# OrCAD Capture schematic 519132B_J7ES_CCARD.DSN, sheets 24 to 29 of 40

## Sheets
24 24. PMIC B: size C; rev: A
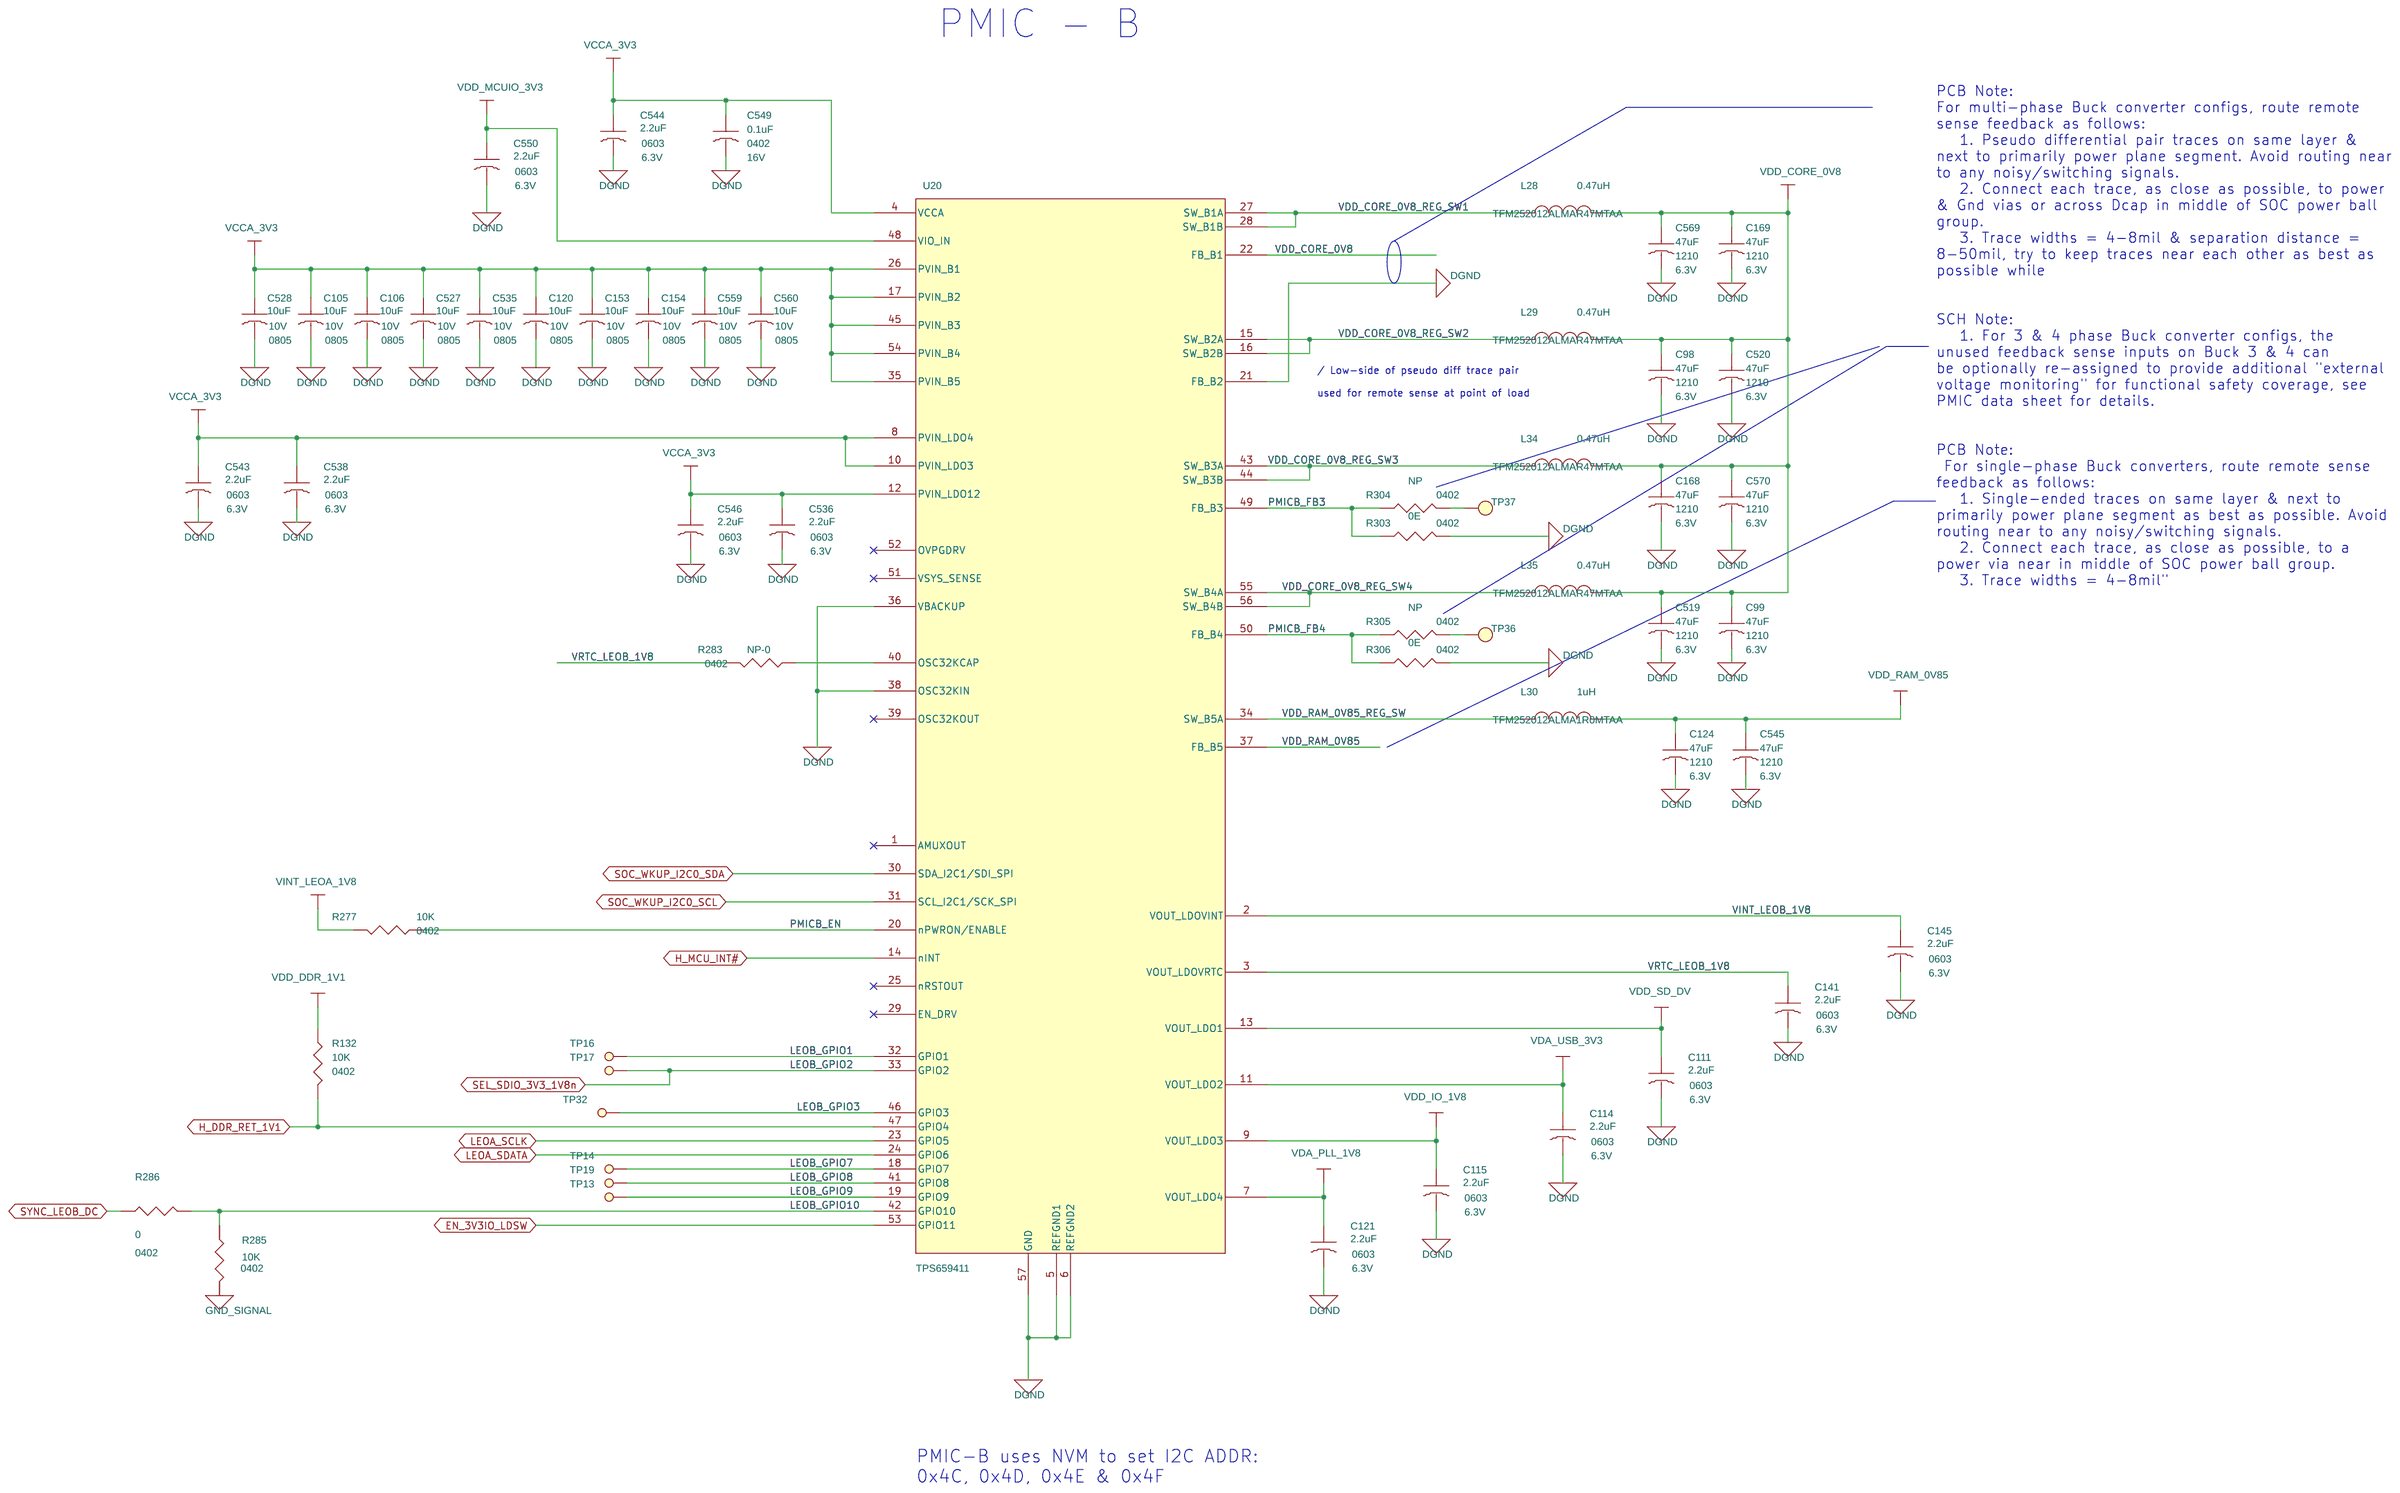
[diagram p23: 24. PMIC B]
25 25. LOAD SWITCHES: size C; rev: A
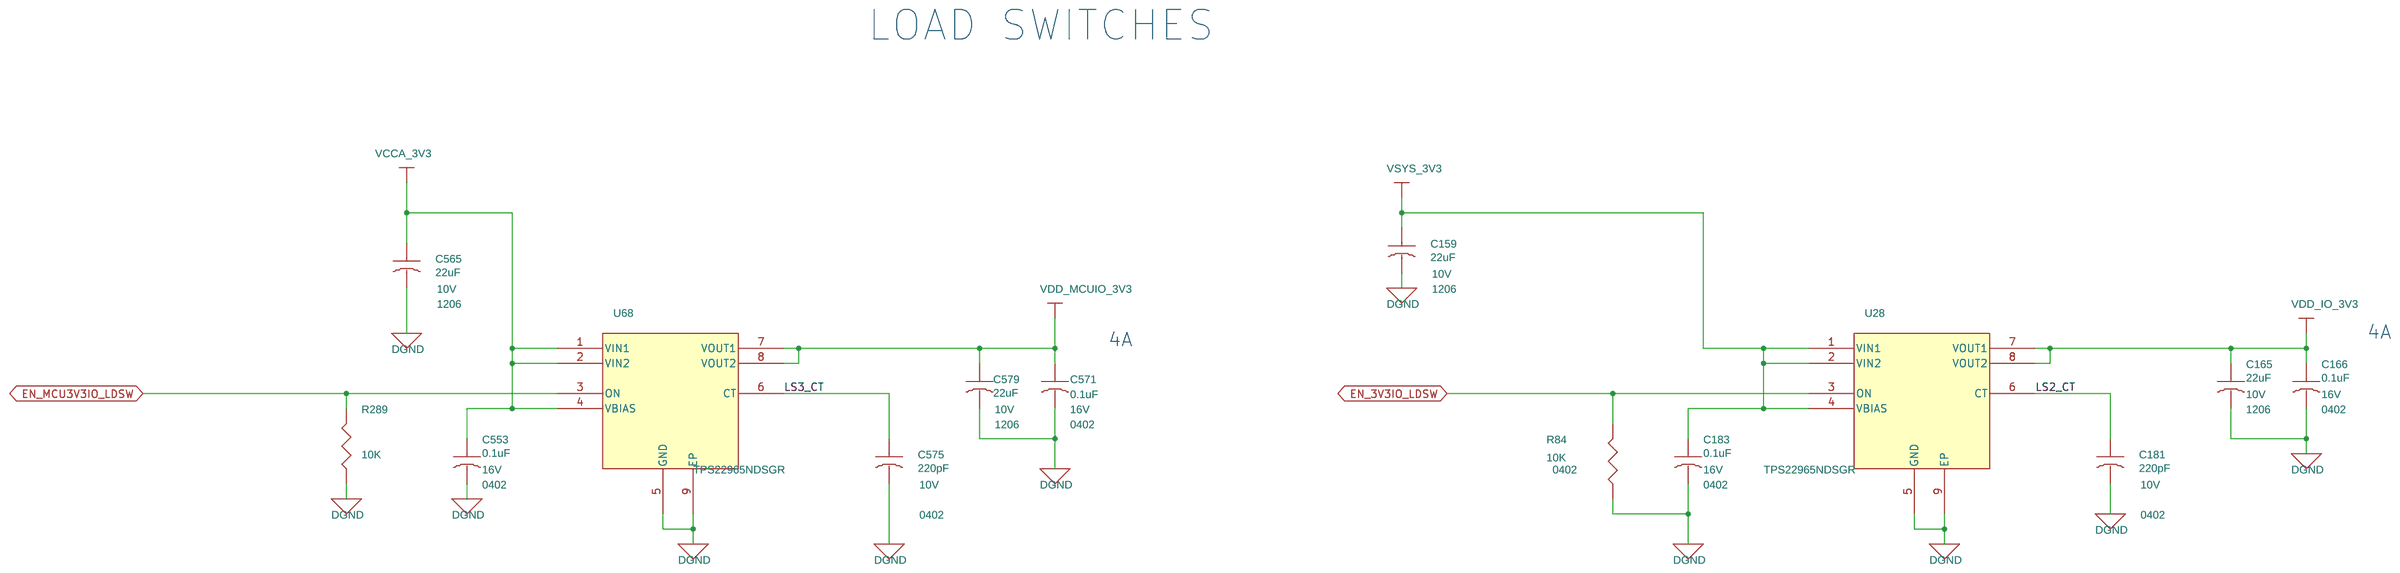
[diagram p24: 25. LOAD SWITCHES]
26 27. BOOTMODE SWITCH: size C; rev: A
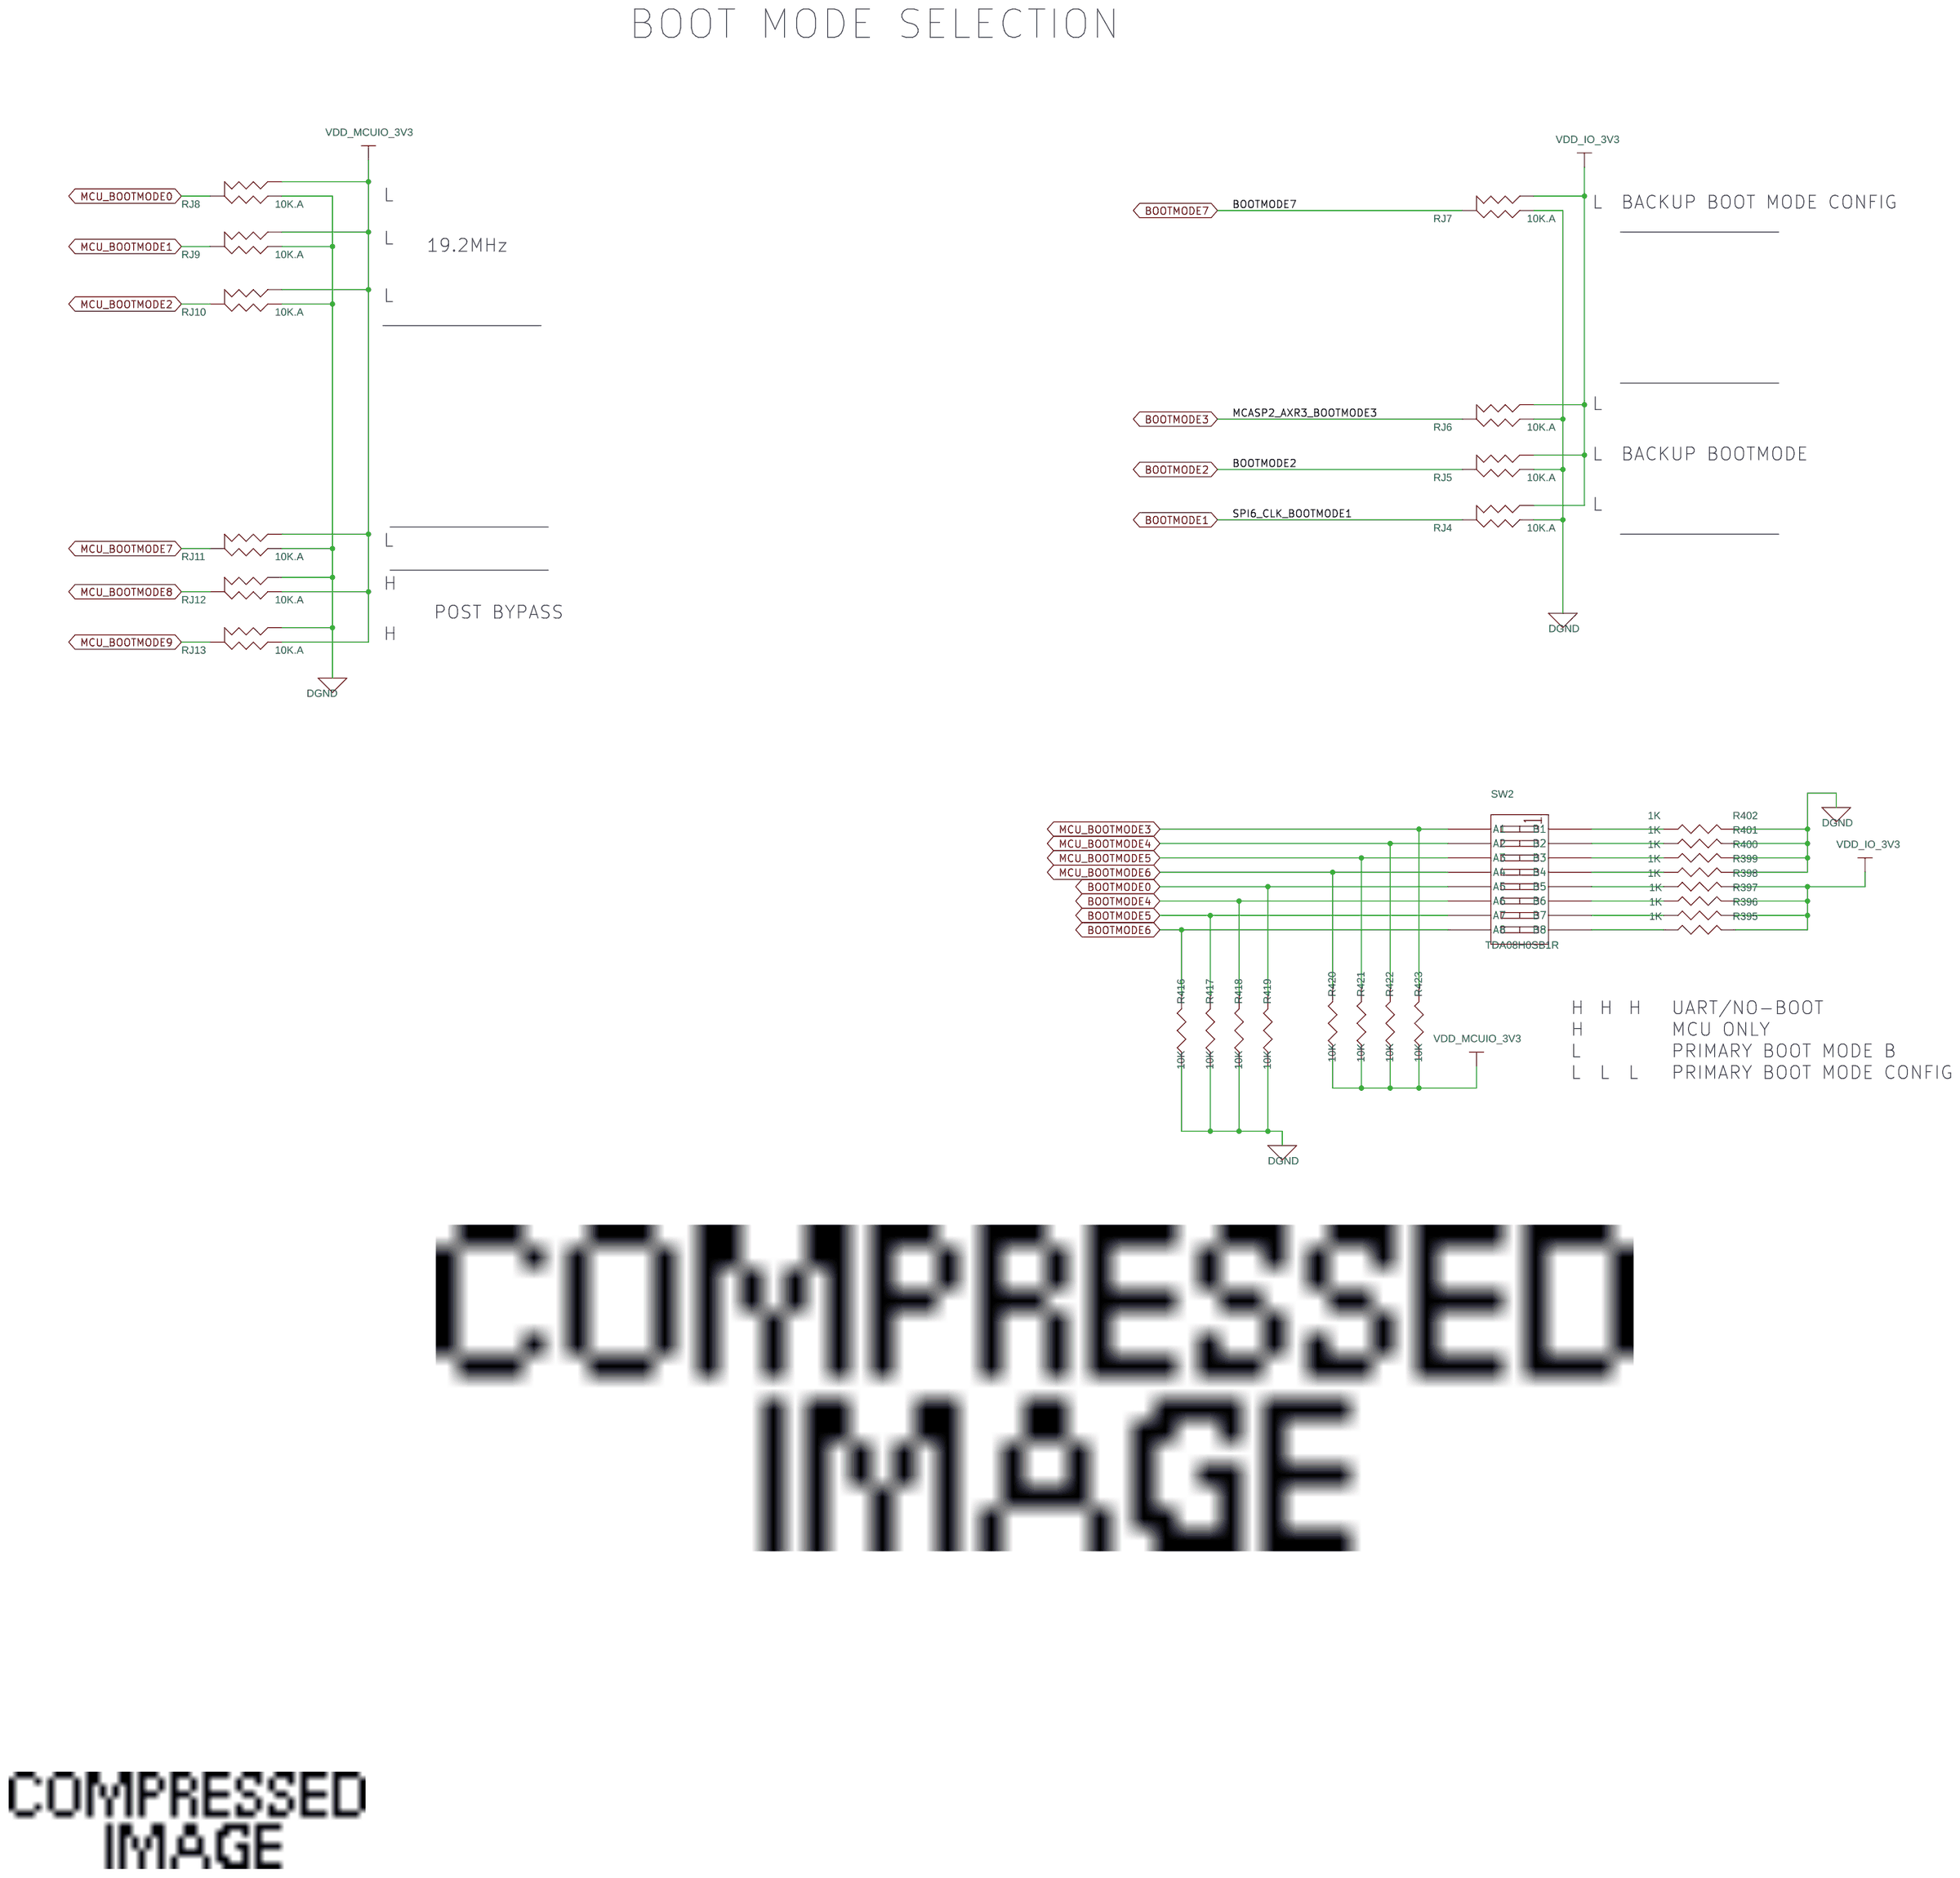
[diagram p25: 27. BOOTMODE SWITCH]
27 28.MEM eMMC: size C; rev: A
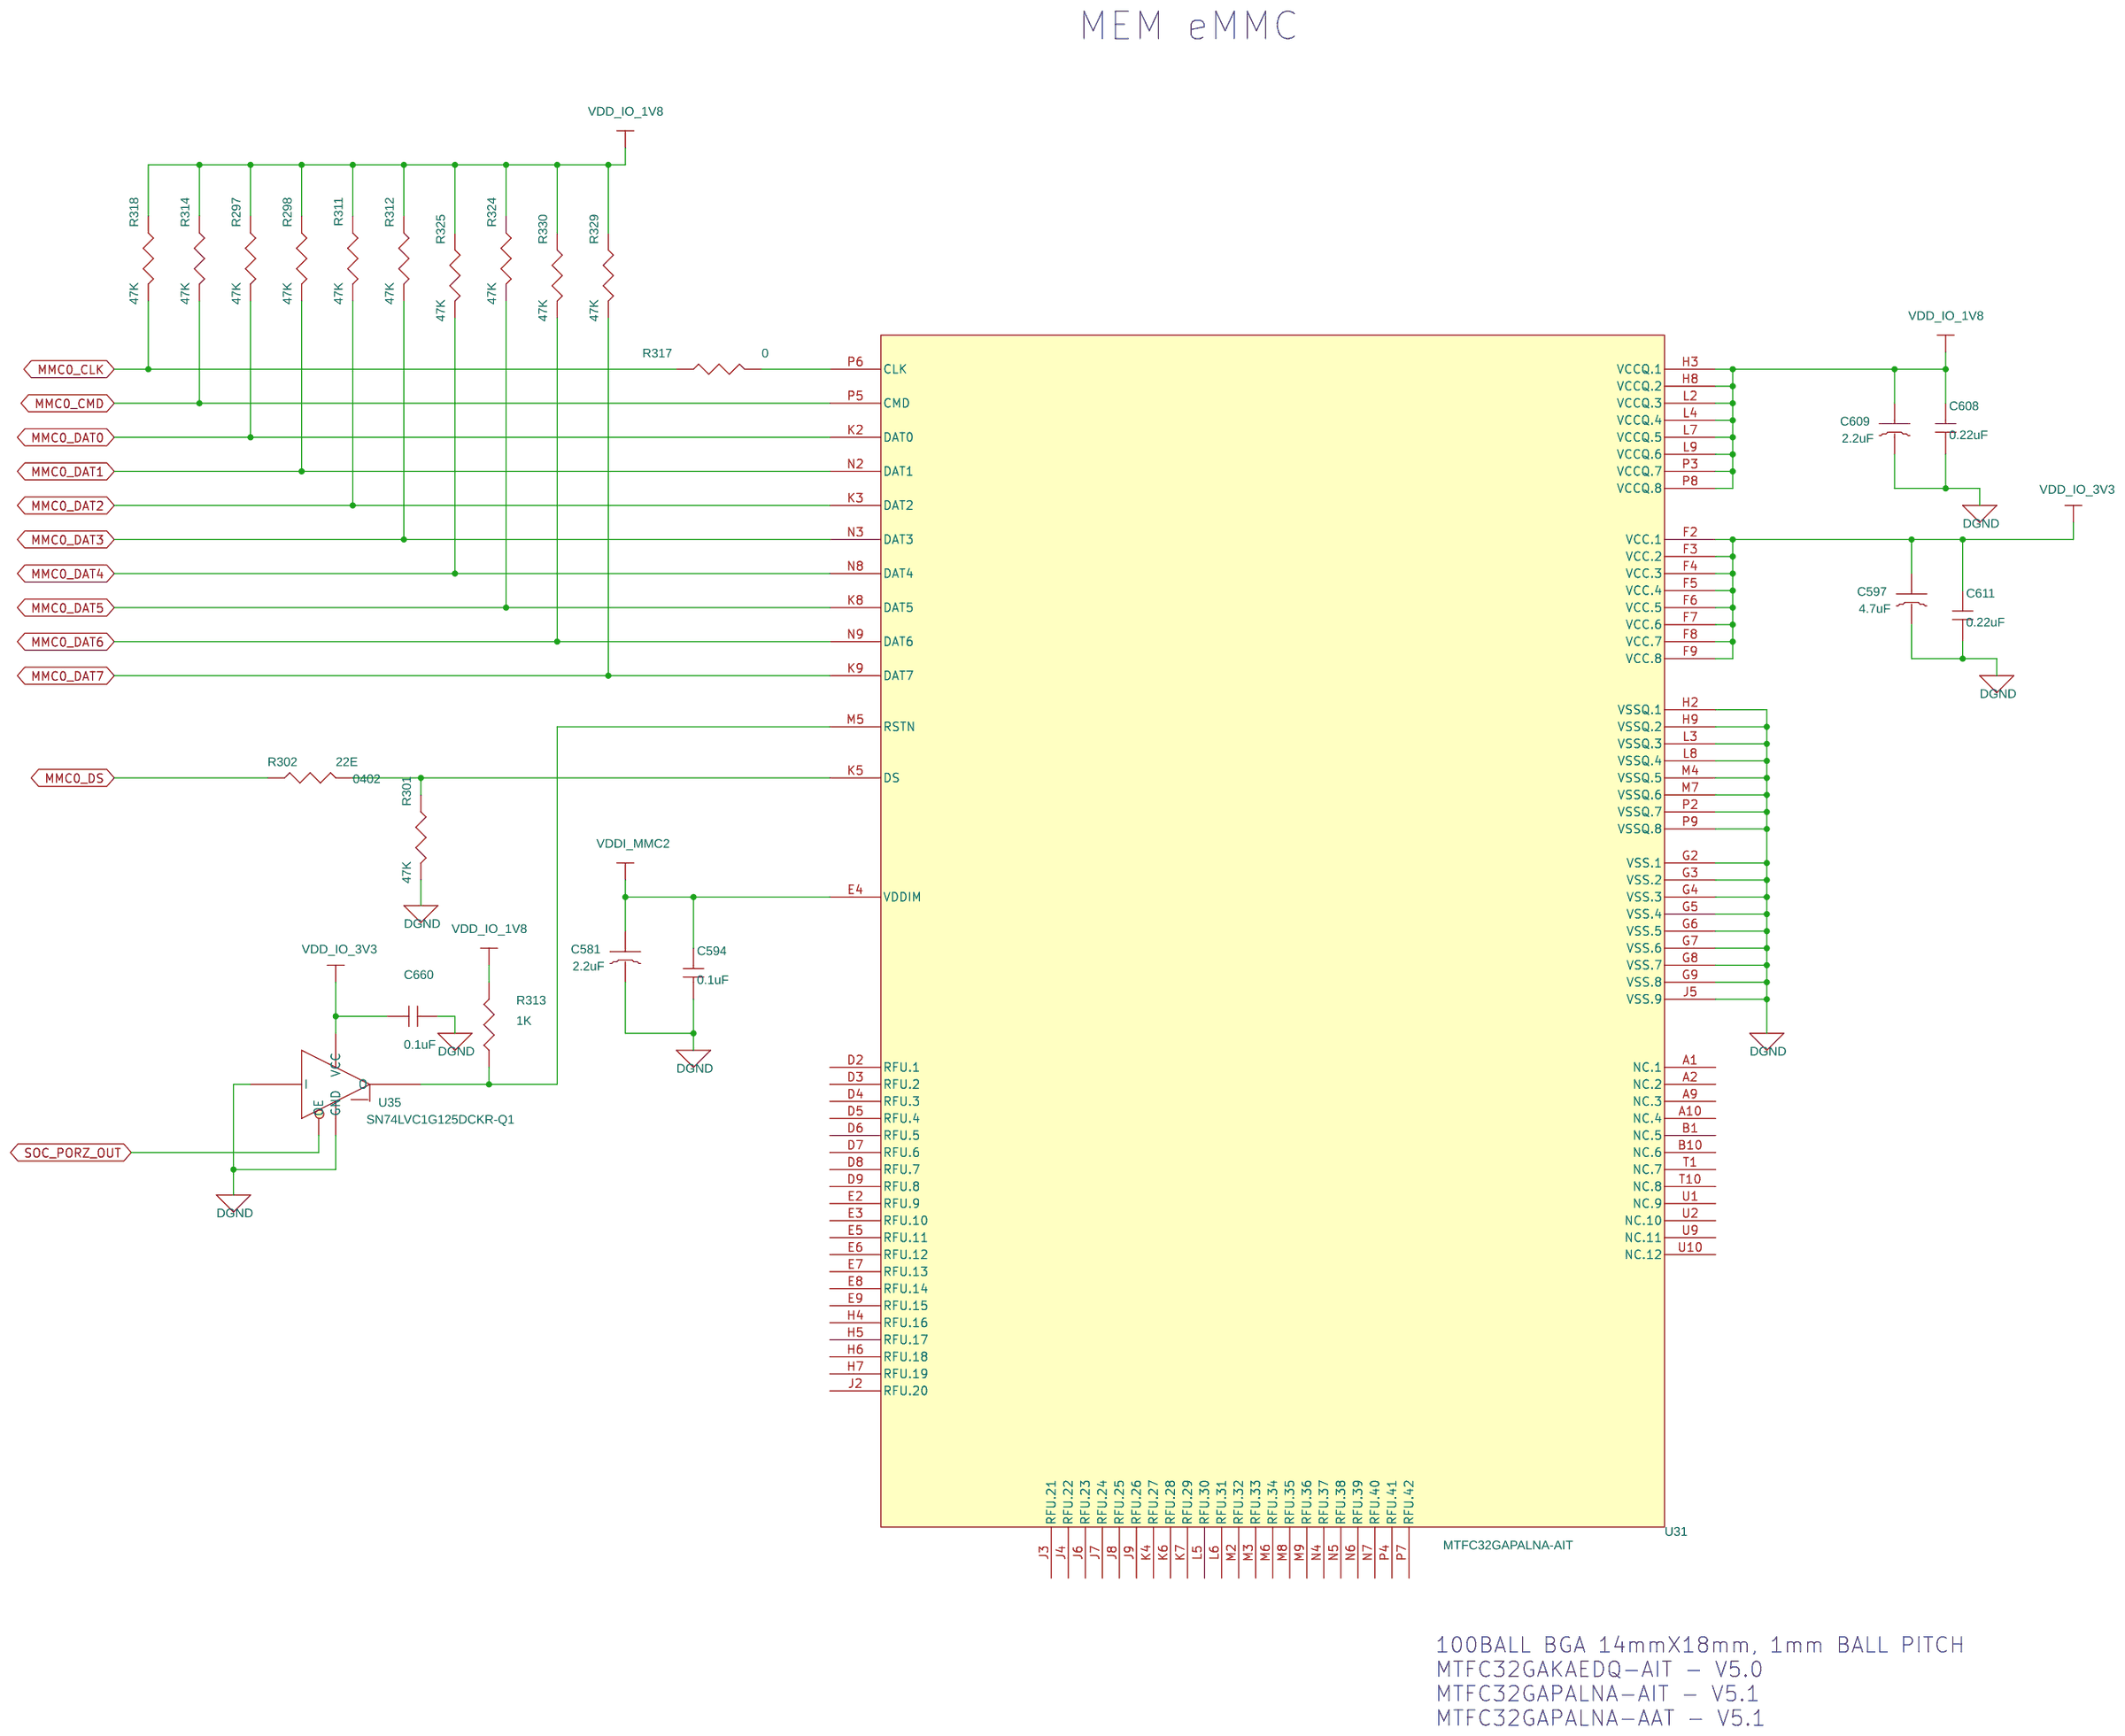
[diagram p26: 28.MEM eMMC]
28 29.USB MEDIA: size C; rev: A
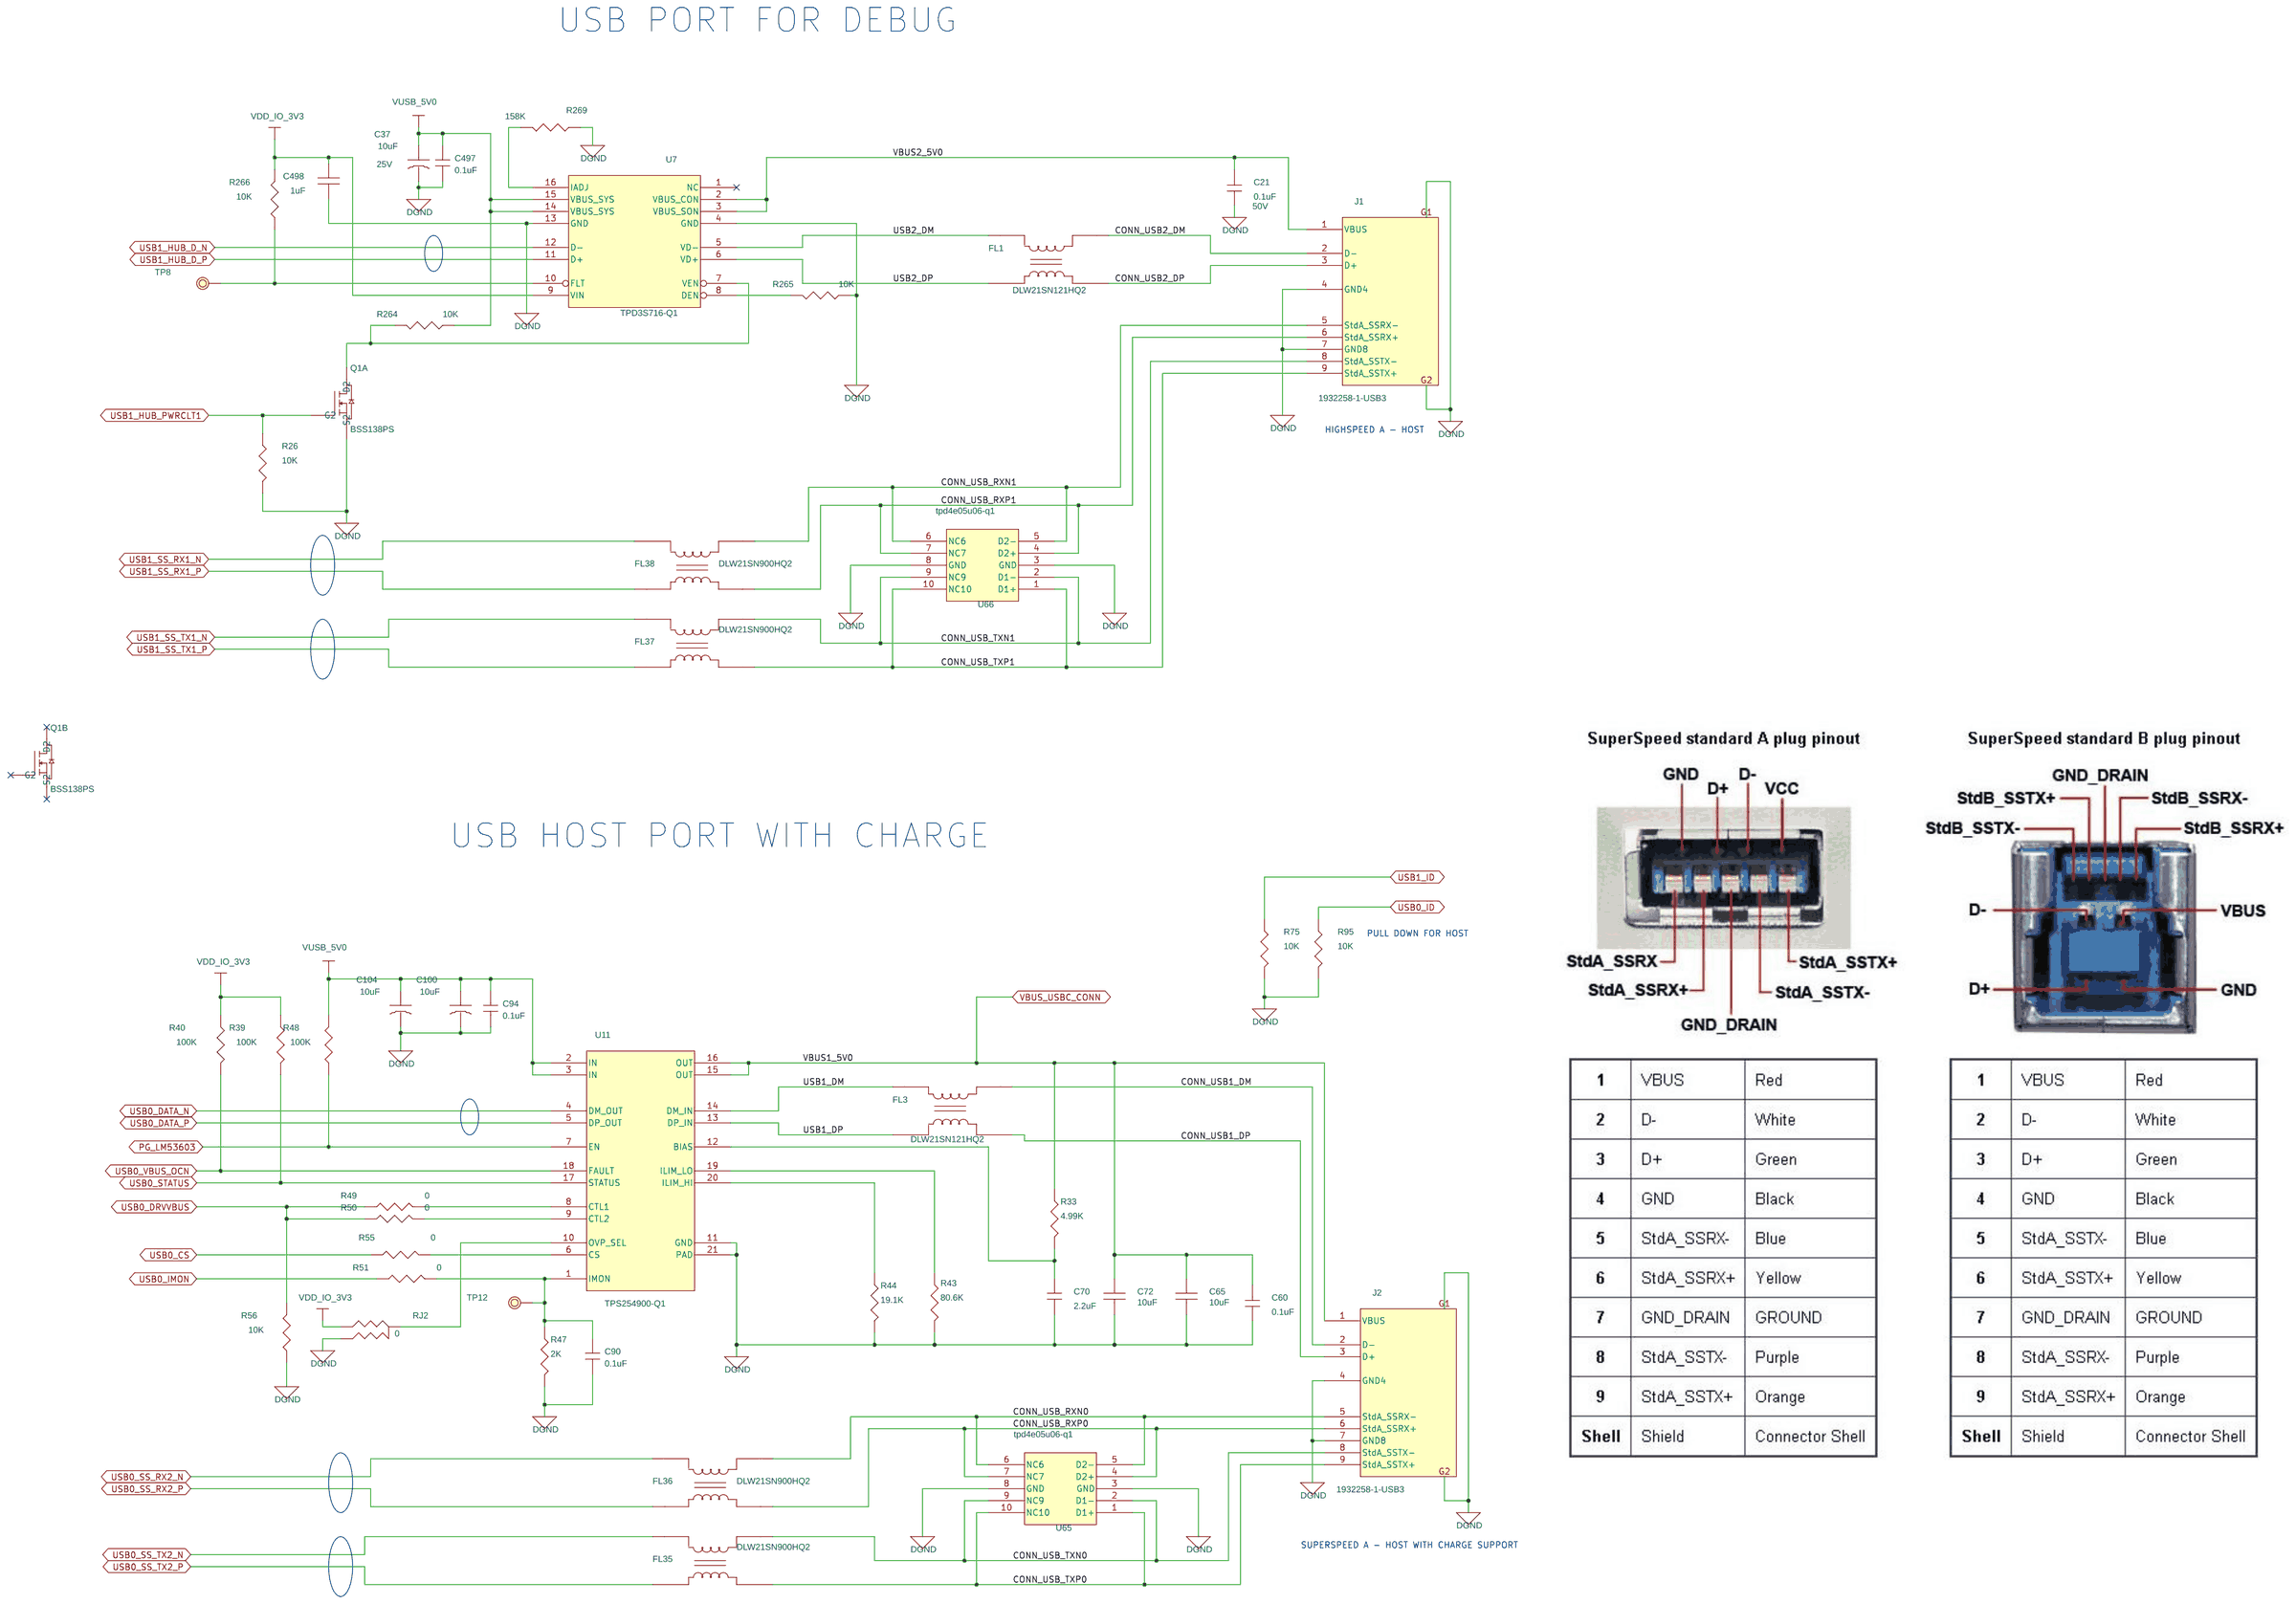
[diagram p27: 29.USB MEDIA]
29 30.DISPLAY PORT INTERFACE: size C; rev: B
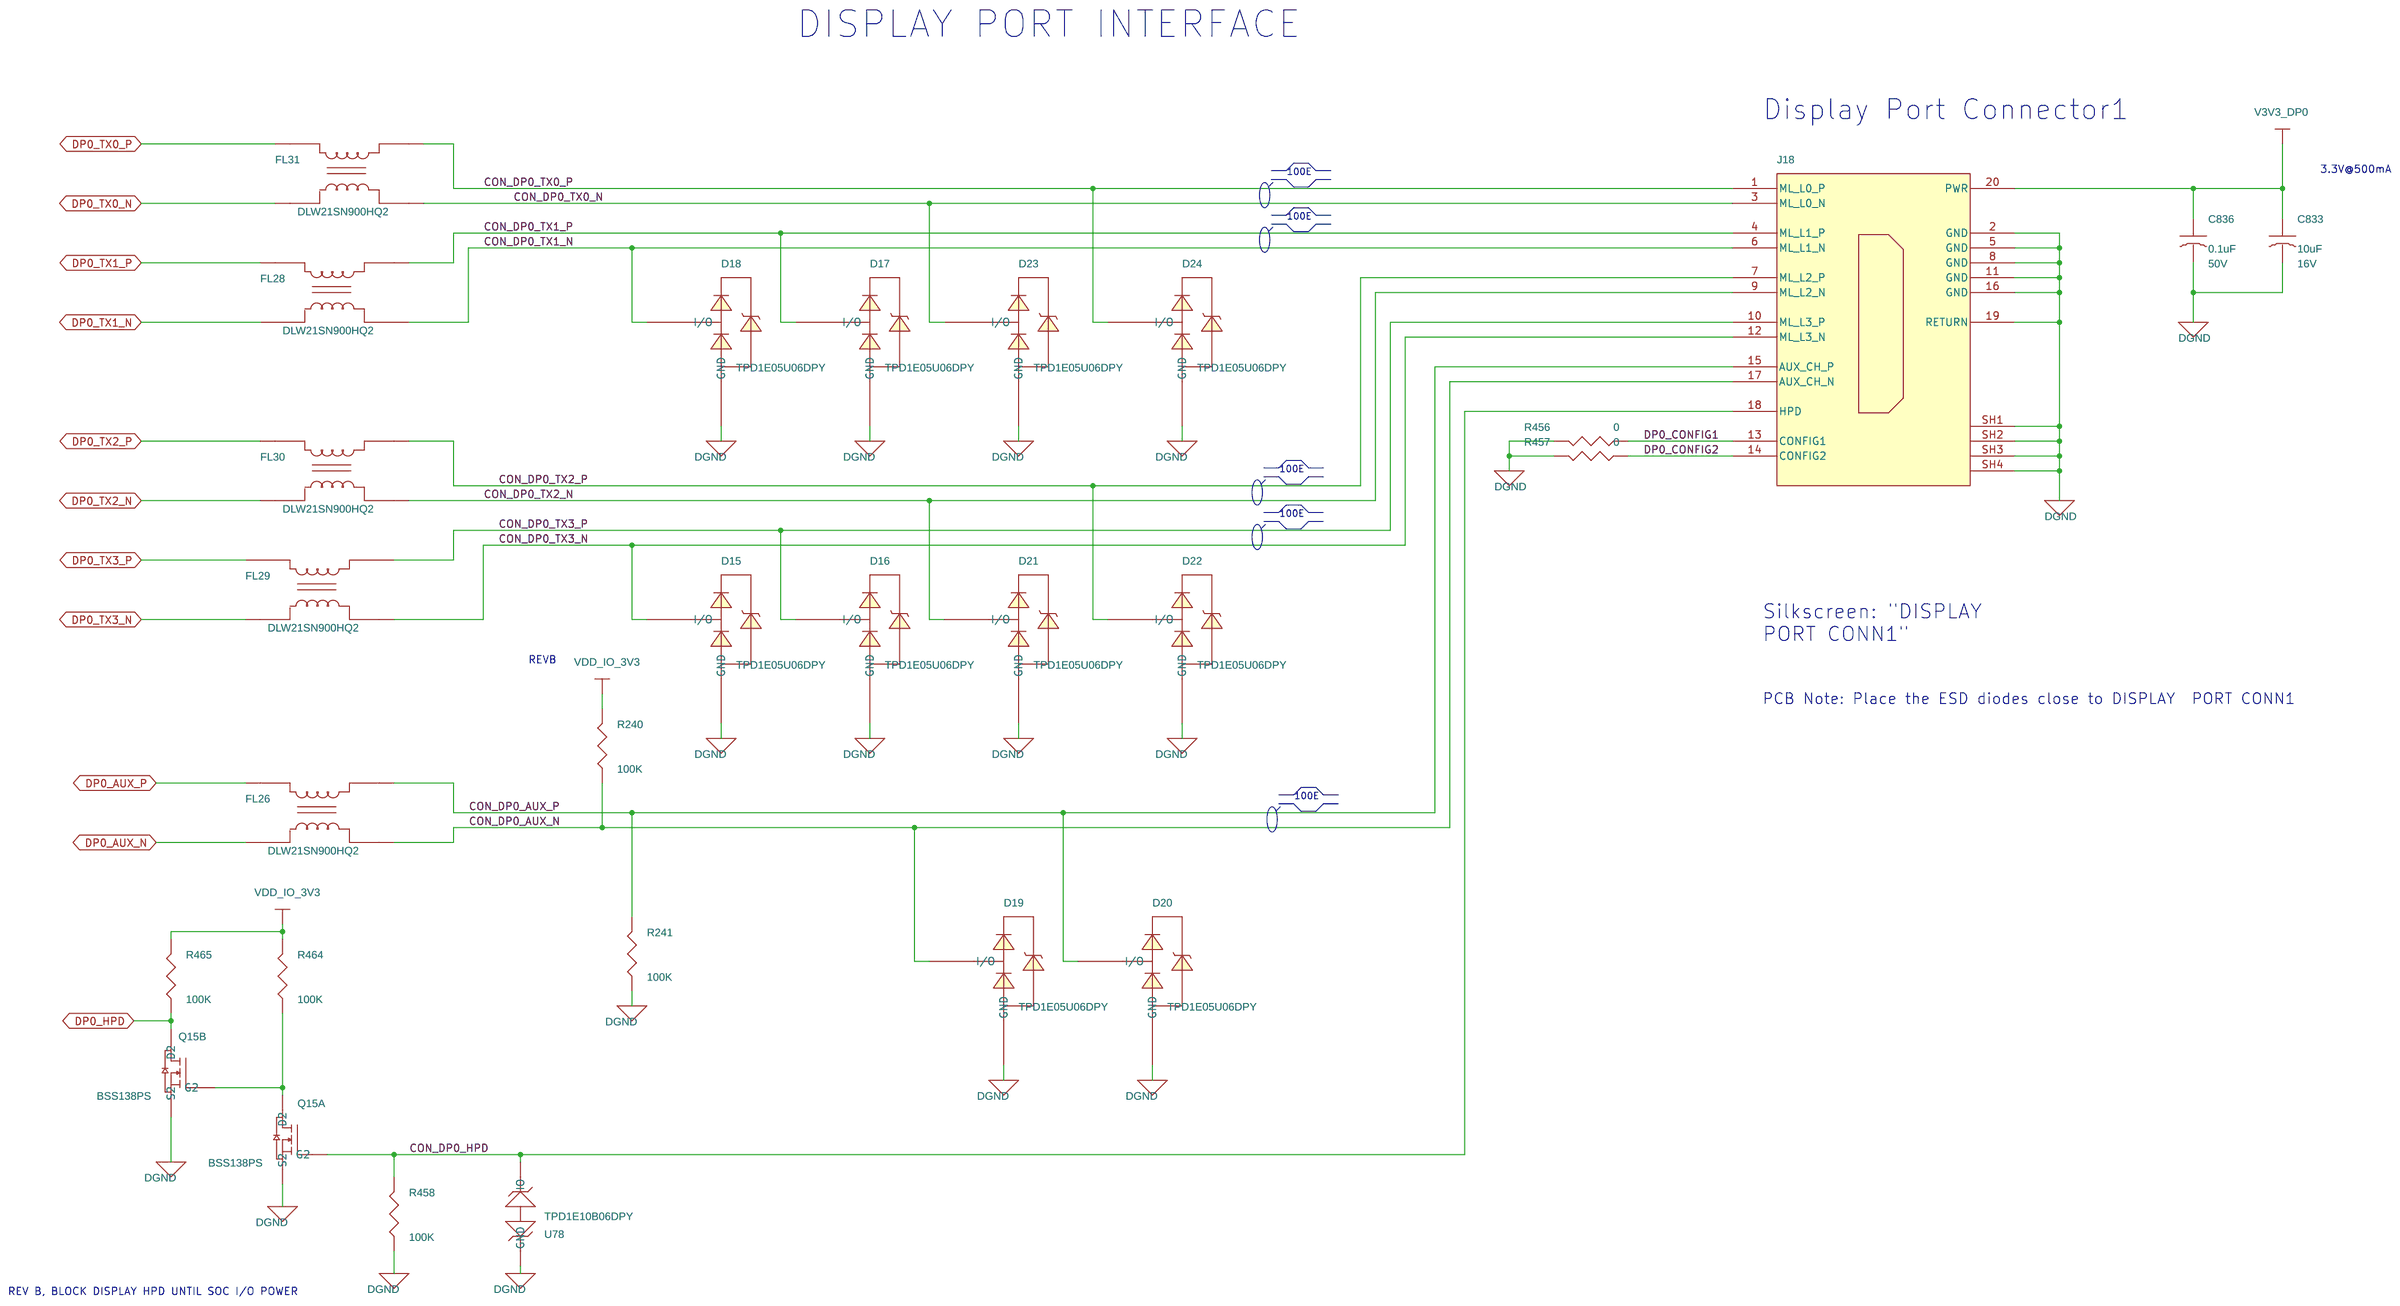
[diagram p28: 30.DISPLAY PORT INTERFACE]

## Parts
sheet 24. PMIC B
C98  47uF  [CAP1210_2-75]
C99  47uF  [CAP1210_2-75]
C105  10uF  [CAP0805_1-5]
C106  10uF  [CAP0805_1-5]
C111  2.2uF  [CAP0603_1]
C114  2.2uF  [CAP0603_1]
C115  2.2uF  [CAP0603_1]
C120  10uF  [CAP0805_1-5]
C121  2.2uF  [CAP0603_1]
C124  47uF  [CAP1210_2-75]
C141  2.2uF  [CAP0603_1]
C145  2.2uF  [CAP0603_1]
C153  10uF  [CAP0805_1-5]
C154  10uF  [CAP0805_1-5]
C168  47uF  [CAP1210_2-75]
C169  47uF  [CAP1210_2-75]
C519  47uF  [CAP1210_2-75]
C520  47uF  [CAP1210_2-75]
C527  10uF  [CAP0805_1-5]
C528  10uF  [CAP0805_1-5]
C535  10uF  [CAP0805_1-5]
C536  2.2uF  [CAP0603_1]
C538  2.2uF  [CAP0603_1]
C543  2.2uF  [CAP0603_1]
C544  2.2uF  [CAP0603_1]
C545  47uF  [CAP1210_2-75]
C546  2.2uF  [CAP0603_1]
C549  0.1uF  [CAP0402_0-75]
C550  2.2uF  [CAP0603_1]
C559  10uF  [CAP0805_1-5]
C560  10uF  [CAP0805_1-5]
C569  47uF  [CAP1210_2-75]
C570  47uF  [CAP1210_2-75]
L28  0.47uH  [IND1008_1-2]
L29  0.47uH  [IND1008_1-2]
L30  1uH  [IND1008_1-2]
L34  0.47uH  [IND1008_1-2]
L35  0.47uH  [IND1008_1-2]
R132  10K  [RES0402_0-5]
R277  10K  [RES0402_0-5]
R283  NP-0  [RES0402_0-5]
R285  10K  [RES0402_0-5]
R286  0  [RES0402_0-5]
R303  0E  [RES0402_0-5]
R304  NP  [RES0402_0-5]
R305  NP  [RES0402_0-5]
R306  0E  [RES0402_0-5]
TP13  TP_VIA_MEM0  [tp-18RD8]
TP14  TP_VIA_MEM0  [tp-18RD8]
TP16  TP_VIA_MEM0  [tp-18RD8]
TP17  TP_VIA_MEM0  [tp-18RD8]
TP19  TP_VIA_MEM0  [tp-18RD8]
TP32  TP_VIA_MEM0  [tp-18RD8]
TP36  TP_VIA_MEM0  [tp-18RD8]
TP37  TP_VIA_MEM0  [tp-18RD8]
U20  TPS659411  [VQFN56_19-68_320X320_0-9_EP6]
sheet 25. LOAD SWITCHES
C159  22uF  [C1206-40X70]
C165  22uF  [C1206-40X70]
C166  0.1uF  [c402-25]
C181  220pF  [c402-25]
C183  0.1uF  [c402-25]
C553  0.1uF  [c402-25]
C565  22uF  [C1206-40X70]
C571  0.1uF  [c402-25]
C575  220pF  [c402-25]
C579  22uF  [C1206-40X70]
R84  10K  [r402-25]
R289  10K  [r402-25]
U28  TPS22965NDSGR  [WSON8_19-68_80X80_0-8]
U68  TPS22965NDSGR  [WSON8_19-68_80X80_0-8]
sheet 27. BOOTMODE SWITCH
R395  1K  [r201-18p5x15]
R396  1K  [r201-18p5x15]
R397  1K  [r201-18p5x15]
R398  1K  [r201-18p5x15]
R399  1K  [r201-18p5x15]
R400  1K  [r201-18p5x15]
R401  1K  [r201-18p5x15]
R402  1K  [r201-18p5x15]
R416  10K  [r201-18p5x15]
R417  10K  [r201-18p5x15]
R418  10K  [r201-18p5x15]
R419  10K  [r201-18p5x15]
R420  10K  [r201-18p5x15]
R421  10K  [r201-18p5x15]
R422  10K  [r201-18p5x15]
R423  10K  [r201-18p5x15]
RJ4  10K.A  [JMP402-25]
RJ5  10K.A  [JMP402-25]
RJ6  10K.A  [JMP402-25]
RJ7  10K.A  [JMP402-25]
RJ8  10K.A  [JMP402-25]
RJ9  10K.A  [JMP402-25]
RJ10  10K.A  [JMP402-25]
RJ11  10K.A  [JMP402-25]
RJ12  10K.A  [JMP402-25]
RJ13  10K.A  [JMP402-25]
SW2  TDA08H0SB1R  [SW8-30X50]
sheet 28.MEM eMMC
C581  2.2uF  [c603-35x45]
C594  0.1uF  [c402-25]
C597  4.7uF  [c603-35x45]
C608  0.22uF  [c603-35x45]
C609  2.2uF  [c603-35x45]
C611  0.22uF  [c603-35x45]
C660  0.1uF  [c402-25]
R297  47K  [r402-25]
R298  47K  [r402-25]
R301  47K  [r402-25]
R302  22E  [r402-25]
R311  47K  [r402-25]
R312  47K  [r402-25]
R313  1K  [r402-25]
R314  47K  [r402-25]
R317  0  [r402-25]
R318  47K  [r402-25]
R324  47K  [r402-25]
R325  47K  [r402-25]
R329  47K  [r402-25]
R330  47K  [r402-25]
U31  MTFC32GAPALNA-AIT  [bga100_1mm]
U35  SN74LVC1G125DCKR-Q1  [dck-5]
sheet 29.USB MEDIA
C21  0.1uF  [c603-35x45]
C37  10uF  [C1206-40X70]
C60  0.1uF  [c603-35x45]
C65  10uF  [C1206-40X70]
C70  2.2uF  [c805-35x60]
C72  10uF  [C1206-40X70]
C90  0.1uF  [c402-25]
C94  0.1uF  [c402-25]
C100  10uF  [C1206-40X70]
C104  10uF  [C1206-40X70]
C497  0.1uF  [c402-25]
C498  1uF  [c402-25]
FL1  DLW21SN121HQ2  [EMI-36X15-DLW21]
FL3  DLW21SN121HQ2  [EMI-36X15-DLW21]
FL35  DLW21SN900HQ2  [EMI-36X15-DLW21-rdpads]
FL36  DLW21SN900HQ2  [EMI-36X15-DLW21-rdpads]
FL37  DLW21SN900HQ2  [EMI-36X15-DLW21-rdpads]
FL38  DLW21SN900HQ2  [EMI-36X15-DLW21-rdpads]
J1  1932258-1-USB3  [con-1932258]
J2  1932258-1-USB3  [con-1932258]
Q1  BSS138PS  [sot363-16x45]  (sections A,B)
R26  10K  [r402-25]
R33  4.99K  [r402-25]
R39  100K  [r402-25]
R40  100K  [r402-25]
R43  80.6K  [r402-25]
R44  19.1K  [r402-25]
R47  2K  [r402-25]
R48  100K  [r402-25]
R49  0  [r402-25]
R50  0  [r402-25]
R51  0  [r402-25]
R55  0  [r402-25]
R56  10K  [r402-25]
R75  10K  [r402-25]
R95  10K  [r402-25]
R264  10K  [r402-25]
R265  10K  [r402-25]
R266  10K  [r402-25]
R269  158K  [r402-25]
RJ2  0  [JMP402-25]
TP8  TP  [tp-30RD13]
TP12  TP  [tp-30RD13]
U7  TPD3S716-Q1  [ssop-16]
U11  TPS254900-Q1  [RVC20]
U65  tpd4e05u06-q1  [dqa-pson10]
U66  tpd4e05u06-q1  [dqa-pson10]
sheet 30.DISPLAY PORT INTERFACE
C833  10uF  [c805-35x60]
C836  0.1uF  [c402-25]
D15  TPD1E05U06DPY  [dpy]
D16  TPD1E05U06DPY  [dpy]
D17  TPD1E05U06DPY  [dpy]
D18  TPD1E05U06DPY  [dpy]
D19  TPD1E05U06DPY  [dpy]
D20  TPD1E05U06DPY  [dpy]
D21  TPD1E05U06DPY  [dpy]
D22  TPD1E05U06DPY  [dpy]
D23  TPD1E05U06DPY  [dpy]
D24  TPD1E05U06DPY  [dpy]
FL26  DLW21SN900HQ2  [EMI-36X15-DLW21-rdpads]
FL28  DLW21SN900HQ2  [EMI-36X15-DLW21-rdpads]
FL29  DLW21SN900HQ2  [EMI-36X15-DLW21-rdpads]
FL30  DLW21SN900HQ2  [EMI-36X15-DLW21-rdpads]
FL31  DLW21SN900HQ2  [EMI-36X15-DLW21-rdpads]
J18  CON_MUSB_20_F  [CON_USB20_472720001_S_R_T_7]
Q15  BSS138PS  [sot363-16x45]  (sections A,B)
R240  100K  [r402-25]
R241  100K  [r402-25]
R456  0  [r402-25]
R457  0  [r402-25]
R458  100K  [r402-25]
R464  100K  [r402-25]
R465  100K  [r402-25]
U78  TPD1E10B06DPY  [dpy]

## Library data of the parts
C98 C99 C124 C168 C169 C519 C520 C545 C569 C570 = CAP: CAP CERAMIC 47uF 6.3V 10% X7R AUTO 1210; Chkd/date: MANIRAJA/280918; Crtd /date: ALVY/280918; Custom_Duty: 15%; Customs_HS_Code: 85322990; Distributor_name: DIGIKEY; Distributor_part_number: 490-4844-1-ND; Footprint Path: Y:\MIS_DATABASE\Library\ALTIUM_TOOL\PCB_FOOTPRINTS\Altium_Footprint_Lib.PcbLib; Footprint Ref: c1210-70x102; Height: 2.70MM; Library Path: Y:\MIS_DATABASE\Library\ALTIUM_TOOL\SCHEMATICS_PARTS\MS_DISCRETE_Library.schlib; MECHANICAL 3D STEP FILE: c1210-70x102; Mfr_name: MURATA; Mfr_part_number: GCM32ER70J476KE19L; Mistral Part No: 120018090056-R; Package: 1210; Part #: 104955-0471R; Part_type: CAPACITORS\CERAMIC; Project: TI_J7_SVB-DUT; RoHS: RoHS; Temperature: -55°C+125°C; Tolerance: 10%; Voltage: 6.3V; Wattage: NA; Weight: 110mg; Datasheet: Y:\MIS_DATABASE\DATASHEETS\CAPACITORS\MURATA-GCM-SER.PDF
C105 C106 C120 C153 C154 C527 C528 C535 C559 C560 = CAP: CAP CERAMIC 10uF 10V 10% X7R AUTO 0805; Chkd/date: MANIRAJA/080419; Crtd /date: ALVY/050419; Custom_Duty: 15%; Customs_HS_Code: 85322990; Distributor_name: DIGIKEY; Distributor_part_number: 490-14531-1-ND; Footprint Path: Y:\MIS_DATABASE\Library\ALTIUM_TOOL\PCB_FOOTPRINTS\Altium_Footprint_Lib.PcbLib; Footprint Ref: c805-35x60; Height: 1.40MM; Library Path: Y:\MIS_DATABASE\Library\ALTIUM_TOOL\SCHEMATICS_PARTS\MS_DISCRETE_Library.schlib; MECHANICAL 3D STEP FILE: c805-35x60; Mfr_name: MURATA; Mfr_part_number: GCM21BR71A106KE22K; Mistral Part No: 120019040010-R; Package: 0805; Part #: 104720-0101R; Part_type: CAPACITORS\CERAMIC; Project: J7ES_SOM_DUAL-LEO_PMIC; RoHS: RoHS; Temperature: -55°C+125°C; Tolerance: 10%; Voltage: 10V; Wattage: NA; Weight: 9.5mg; Datasheet: Y:\MIS_DATABASE\DATASHEETS\CAPACITORS\GCM21BR71A106KE22.PDF
C111 C114 C115 C121 C141 C145 C536 C538 C543 C544 C546 C550 = CAP: CAP CERAMIC 2.2uF 6.3V 10% X7R AUTO 0603; Chkd/date: MANIRAJA/050419; Crtd /date: ALVY/050419; Custom_Duty: 15%; Customs_HS_Code: 85322990; Distributor_name: DIGIKEY; Distributor_part_number: 490-5316-1-ND; Footprint Path: Y:\MIS_DATABASE\Library\ALTIUM_TOOL\PCB_FOOTPRINTS\Altium_Footprint_Lib.PcbLib; Footprint Ref: c603-35x45; Height: 0.90MM; Library Path: Y:\MIS_DATABASE\Library\ALTIUM_TOOL\SCHEMATICS_PARTS\MS_DISCRETE_Library.schlib; MECHANICAL 3D STEP FILE: c603-35x45; Mfr_name: MURATA; Mfr_part_number: GCM188R70J225KE22D; Mistral Part No: 120019040009-R; Package: 0603; Part #: 104448-0220R; Part_type: CAPACITORS\CERAMIC; Project: J7ES_SOM_DUAL-LEO_PMIC; RoHS: RoHS; Temperature: -55°C+125°C; Tolerance: 10%; Voltage: 6.3V; Wattage: NA; Weight: 6.3mg; Datasheet: Y:\MIS_DATABASE\DATASHEETS\CAPACITORS\GCM188R70J225KE22.PDF
C549 = CAP: CAP CERAMIC 0.1uF 16V 10% X7R AUTO 0402; Chkd/date: NAVEED/021014; Crtd /date: VASANTHA/300514; Custom_Duty: 15%; Customs_HS_Code: 85322990; Distributor_name: DIGIKEY; Distributor_part_number: 490-4759-1-ND; Footprint Path: Y:\MIS_DATABASE\Library\ALTIUM_TOOL\PCB_FOOTPRINTS\Altium_Footprint_Lib.PcbLib; Footprint Ref: c402-25; Height: 0.55MM; Library Path: Y:\MIS_DATABASE\Library\ALTIUM_TOOL\SCHEMATICS_PARTS\MS_DISCRETE_Library.schlib; MECHANICAL 3D STEP FILE: c402-25; Mfr_name: MURATA; Mfr_part_number: GCM155R71C104KA55D; Mistral Part No: 120016070006-R; Package: 0402; Part #: 104446-1100R; Part_type: CAPACITORS\CERAMIC; Project: DCMIST_FPGA_CARD; RoHS: RoHS; Temperature: -55°C+125°C; Tolerance: 10%; Voltage: 16V; Wattage: NA; Weight: 6mg; Datasheet: Y:\MIS_DATABASE\DATASHEETS\CAPACITORS\MURATA-GCM-SER.PDF
L28 L29 L34 L35 = INDUCTOR: IND POWER 0.47uH 20% 4.9A 1008; Chkd/date: VASANTHA/010419; Crtd /date: ALVY/010419; Custom_Duty: 24%; Customs_HS_Code: 85437099; Distributor_name: DIGIKEY; Distributor_part_number: 445-181489-1-ND; Footprint Path: Y:\MIS_DATABASE\Library\ALTIUM_TOOL\PCB_FOOTPRINTS\Altium_Footprint_Lib.PcbLib; Height: 1.20MM; Library Path: Y:\MIS_DATABASE\Library\ALTIUM_TOOL\SCHEMATICS_PARTS\MS_DISCRETE_Library.schlib; Mfr_name: TDK CORPORATION; Mfr_part_number: TFM252012ALMAR47MTAA; Mistral Part No: 130019040001-R; Package: 1008; Part #: 105324-1470R; Project: J7ES_SOM_DUAL-LEO_PMIC; RoHS: RoHS; Temperature: -55°C+150°C; Tolerance: 20%; Voltage: NA; Wattage: NA; Weight: NA; Datasheet: Y:\MIS_DATABASE\DATASHEETS\DISCRETES\INDUCTORS\TFM252012ALMA-SER.PDF
L30 = INDUCTOR: IND POWER 1uH 3.7A 20% AUTO 1008; Chkd/date: MANIRAJA/160419; Crtd /date: MANIRAJA/160419; Custom_Duty: 24%; Customs_HS_Code: 85437099; Distributor_name: DIGIKEY; Distributor_part_number: 445-175183-1-ND; Footprint Path: Y:\MIS_DATABASE\Library\ALTIUM_TOOL\PCB_FOOTPRINTS\Altium_Footprint_Lib.PcbLib; Height: 1.20MM; Library Path: Y:\MIS_DATABASE\Library\ALTIUM_TOOL\SCHEMATICS_PARTS\MS_DISCRETE_Library.schlib; Mfr_name: TDK CORPORATION; Mfr_part_number: TFM252012ALMA1R0MTAA; Mistral Part No: 130019040010-R; Package: 1008; Part #: 105324-0100R; Project: J7ES_SOM_DUAL-LEO_PMIC; RoHS: RoHS; Temperature: -55°C+150°C; Tolerance: 20%; Voltage: NA; Wattage: NA; Weight: 35mg; Datasheet: Y:\MIS_DATABASE\DATASHEETS\DISCRETES\INDUCTORS\TFM252012ALMA-SER.PDF
R132 R277 = RESISTOR: RES 10K 1/16W 1% 0402; Chkd/date: VASANTHA/201216; Crtd /date: GEETHA/290506; Custom_Duty: 15%; Customs_HS_Code: 85332119; Distributor_name: DIGIKEY; Distributor_part_number: 311-10.0KLRTR-ND; Footprint Path: Y:\MIS_DATABASE\Library\ALTIUM_TOOL\PCB_FOOTPRINTS\Altium_Footprint_Lib.PcbLib; Footprint Ref: r402-25; Height: 0.40MM; Library Path: Y:\MIS_DATABASE\Library\ALTIUM_TOOL\SCHEMATICS_PARTS\MS_DISCRETE_Library.schlib; MECHANICAL 3D STEP FILE: r402-25; Mfr_name: YAGEO AMERICA; Mfr_part_number: RC0402FR-0710KL; Mistral Part No: 110015090015-R; Package: 0402; Part #: 102145-1003R; Part_type: RESISTORS\FIXED; Project: VOCERA; RoHS: RoHS; Temperature: -55°C+155°C; Tolerance: 1%; Voltage: NA; Wattage: 1/16W; Weight: 0.65mg; Datasheet: Y:\MIS_DATABASE\DATASHEETS\RESISTORS\RCXXXXL-SER_MAR18.PDF
R283 = RESISTOR: RES 0E 1/10W JUMPER 0402; Chkd/date: VASANTHA/061216; Crtd /date: NAVEED/201014; Custom_Duty: 15%; Customs_HS_Code: 85332119; Distributor_name: DIGIKEY; Distributor_part_number: P0.0JCT-ND; Footprint Path: Y:\MIS_DATABASE\Library\ALTIUM_TOOL\PCB_FOOTPRINTS\Altium_Footprint_Lib.PcbLib; Footprint Ref: r402-25; Height: 0.40MM; IBISSP_MODLES: VALUE REPEATING 2 TIME; Library Path: Y:\MIS_DATABASE\Library\ALTIUM_TOOL\SCHEMATICS_PARTS\MS_DISCRETE_Library.schlib; MECHANICAL 3D STEP FILE: r402-25; Mfr_name: PANASONIC-ECG; Mfr_part_number: ERJ-2GE0R00X; Mistral Part No: 110018030052-R; Package: 0402; Part #: R0402-NOPOP; Part_type: RESISTORS\FIXED; Project: AEGIS POM; RoHS: RoHS; Temperature: -55°C+155°C; Tolerance: NA; Voltage: NA; Wattage: 1/10W; Weight: 0.8mg; Datasheet: Y:\MIS_DATABASE\DATASHEETS\RESISTORS\PAN-ERJSER_NOV17.PDF
R285 = RESISTOR: RES 0E 1/10W JUMPER 0402; Chkd/date: VASANTHA/061216; Crtd /date: NAVEED/201014; Custom_Duty: 15%; Customs_HS_Code: 85332119; Distributor_name: DIGIKEY; Distributor_part_number: P0.0JCT-ND; Footprint Path: Y:\MIS_DATABASE\Library\ALTIUM_TOOL\PCB_FOOTPRINTS\Altium_Footprint_Lib.PcbLib; Footprint Ref: r402-25; Height: 0.40MM; IBISSP_MODLES: VALUE REPEATING 2 TIME; Library Path: Y:\MIS_DATABASE\Library\ALTIUM_TOOL\SCHEMATICS_PARTS\MS_DISCRETE_Library.schlib; MECHANICAL 3D STEP FILE: r402-25; Mfr_name: PANASONIC-ECG; Mfr_part_number: ERJ-2GE0R00X; Mistral Part No: 110018030052-R; Package: 0402; Part #: 102145-1003R; Part_type: RESISTORS\FIXED; Project: AEGIS POM; RoHS: RoHS; Temperature: -55°C+155°C; Tolerance: NA; Voltage: NA; Wattage: 1/10W; Weight: 0.8mg; Datasheet: Y:\MIS_DATABASE\DATASHEETS\RESISTORS\PAN-ERJSER_NOV17.PDF
R286 = RESISTOR: RES 0E 1/10W JUMPER 0402; Chkd/date: VASANTHA/061216; Crtd /date: NAVEED/201014; Custom_Duty: 15%; Customs_HS_Code: 85332119; Distributor_name: DIGIKEY; Distributor_part_number: P0.0JCT-ND; Footprint Path: Y:\MIS_DATABASE\Library\ALTIUM_TOOL\PCB_FOOTPRINTS\Altium_Footprint_Lib.PcbLib; Footprint Ref: r402-25; Height: 0.40MM; IBISSP_MODLES: VALUE REPEATING 2 TIME; Library Path: Y:\MIS_DATABASE\Library\ALTIUM_TOOL\SCHEMATICS_PARTS\MS_DISCRETE_Library.schlib; MECHANICAL 3D STEP FILE: r402-25; Mfr_name: PANASONIC-ECG; Mfr_part_number: ERJ-2GE0R00X; Mistral Part No: 110018030052-R; Package: 0402; Part #: 101370-0001R; Part_type: RESISTORS\FIXED; Project: AEGIS POM; RoHS: RoHS; Temperature: -55°C+155°C; Tolerance: NA; Voltage: NA; Wattage: 1/10W; Weight: 0.8mg; Datasheet: Y:\MIS_DATABASE\DATASHEETS\RESISTORS\PAN-ERJSER_NOV17.PDF
R303 R306 R456 R457 = RESISTOR: RES 0E 1/10W JUMPER 0402; Chkd/date: VASANTHA/061216; Crtd /date: NAVEED/201014; Custom_Duty: 15%; Customs_HS_Code: 85332119; Distributor_name: DIGIKEY; Distributor_part_number: P0.0JCT-ND; Footprint Path: Y:\MIS_DATABASE\Library\ALTIUM_TOOL\PCB_FOOTPRINTS\Altium_Footprint_Lib.PcbLib; Height: 0.40MM; IBISSP_MODLES: VALUE REPEATING 2 TIME; Library Path: Y:\MIS_DATABASE\Library\ALTIUM_TOOL\SCHEMATICS_PARTS\MS_DISCRETE_Library.schlib; Mfr_name: PANASONIC-ECG; Mfr_part_number: ERJ-2GE0R00X; Mistral Part No: 110018030052-R; Package: 0402; Part #: 101370-0001R; Part_type: RESISTORS\FIXED; Project: AEGIS POM; RoHS: RoHS; Temperature: -55°C+155°C; Tolerance: NA; Voltage: NA; Wattage: 1/10W; Weight: 0.8mg; Datasheet: Y:\MIS_DATABASE\DATASHEETS\RESISTORS\PAN-ERJSER_NOV17.PDF
R304 R305 = RESISTOR: RES 0E 1/10W JUMPER 0402; Chkd/date: VASANTHA/061216; Crtd /date: NAVEED/201014; Custom_Duty: 15%; Customs_HS_Code: 85332119; Distributor_name: DIGIKEY; Distributor_part_number: P0.0JCT-ND; Footprint Path: Y:\MIS_DATABASE\Library\ALTIUM_TOOL\PCB_FOOTPRINTS\Altium_Footprint_Lib.PcbLib; Height: 0.40MM; IBISSP_MODLES: VALUE REPEATING 2 TIME; Library Path: Y:\MIS_DATABASE\Library\ALTIUM_TOOL\SCHEMATICS_PARTS\MS_DISCRETE_Library.schlib; Mfr_name: PANASONIC-ECG; Mfr_part_number: ERJ-2GE0R00X; Mistral Part No: 110018030052-R; Package: 0402; Part #: R0402-NOPOP; Part_type: RESISTORS\FIXED; Project: AEGIS POM; RoHS: RoHS; Temperature: -55°C+155°C; Tolerance: NA; Voltage: NA; Wattage: 1/10W; Weight: 0.8mg; Datasheet: Y:\MIS_DATABASE\DATASHEETS\RESISTORS\PAN-ERJSER_NOV17.PDF
TP13 TP14 TP16 TP17 TP19 TP32 = TP_VIA_MEM0_0: Part #: TP-18RD8-NO-POP
TP36 TP37 = TESTPOINT: TESTPOINT CIR 40 SMD; Chkd/date: MAZHAR/190505; Crtd /date: MAZHAR/190505; Distributor_name: NA; Distributor_part_number: NA; Footprint Path: Y:\MIS_DATABASE\Library\ALTIUM_TOOL\PCB_FOOTPRINTS\Altium_Footprint_Lib.PcbLib; Footprint Ref: TP40_SMD; Height: NA; Library Path: Y:\MIS_DATABASE\Library\ALTIUM_TOOL\SCHEMATICS_PARTS\MS_DISCRETE_Library.schlib; MECHANICAL 3D STEP FILE: NA; Mfr_name: LOCAL; Mfr_part_number: TP40_SMD; Mistral Part No: 130009030933; Package: SMD; Part #: TP-18RD8-NO-POP; Project: RAINIER-3; RoHS: NA; Temperature: NA; Tolerance: NA; Voltage: NA; Wattage: NA; Weight: NA; Datasheet: NA
U20 = TPS65941-Q1_VQFN56_0: IC POWER MANAGEMENT WITH 4-PHASE 14A BUCK VQFN56; Chkd/date: MANIRAJA/310519; Crtd /date: MANIRAJA/310519; Custom_Duty: 15%; Customs_HS_Code: 85423100; Distributor_name: NA; Distributor_part_number: NA; Footprint Path: Y:\MIS_DATABASE\Library\ALTIUM_TOOL\PCB_FOOTPRINTS\Altium_Footprint_Lib.PcbLib; Height: 0.90MM; Library Path: Y:\MIS_DATABASE\Library\ALTIUM_TOOL\SCHEMATICS_PARTS\MS_MISCPOWER_Library.schlib; Library Ref: TPS65941-Q1_VQFN56; Mfr_name: TEXAS INSTRUMENTS; Mistral Part No: 142019050028-R; Package: VQFN56; Part #: 105328-0001R-TI; Part_type: ICS\POWER\MANAGEMENT; Project: J7ES_SOM_DUAL-LEO_PMIC; RoHS: RoHS; Temperature: -40°C+125°C; Tolerance: NA; Voltage: NA; Wattage: NA; Weight: NA; Datasheet: Y:\MIS_DATABASE\DATASHEETS\ICS\POWER\TPS65941-Q1.PDF
C159 C165 C565 C579 = CAP: CAP CERAMIC 22uF 10V 20% X7R 1206; Chkd/date: MANIRAJA/070319; Crtd /date: ALVY/070319; Custom_Duty: 15%; Customs_HS_Code: 85322990; Distributor_name: DIGIKEY; Distributor_part_number: 587-2782-1-ND; Footprint Path: Y:\MIS_DATABASE\Library\ALTIUM_TOOL\PCB_FOOTPRINTS\Altium_Footprint_Lib.PcbLib; Height: 1.80MM; Library Path: Y:\MIS_DATABASE\Library\ALTIUM_TOOL\SCHEMATICS_PARTS\MS_DISCRETE_Library.schlib; Mfr_name: TAIYO YUDEN; Mfr_part_number: LMK316AB7226ML-TR; Mistral Part No: 120019030002-R; Package: 1206; Part #: 105318-0221R; Part_type: CAPACITORS\CERAMIC; Project: TI_J7ES_EVM_SOM; RoHS: RoHS; Temperature: -55°C+125°C; Tolerance: 20%; Voltage: 10V; Wattage: NA; Weight: 16.2mg; Datasheet: Y:\MIS_DATABASE\DATASHEETS\CAPACITORS\LMK316AB7226ML-TR.PDF
C166 C183 C553 C571 = CAP: CAP CERAMIC 0.1uF 16V 5% X7R AUTO 0402; Chkd/date: MANIRAJA/241018; Crtd /date: ALVY/241018; Custom_Duty: 15%; Customs_HS_Code: 85322990; Distributor_name: DIGIKEY; Distributor_part_number: 490-16433-1-ND; Footprint Path: Y:\MIS_DATABASE\Library\ALTIUM_TOOL\PCB_FOOTPRINTS\Altium_Footprint_Lib.PcbLib; Height: 0.55MM; Library Path: Y:\MIS_DATABASE\Library\ALTIUM_TOOL\SCHEMATICS_PARTS\MS_DISCRETE_Library.schlib; Mfr_name: MURATA; Mfr_part_number: GCM155R71C104JA55D; Mistral Part No: 120018100055-R; Package: 0402; Part #: 104446-1100R; Part_type: CAPACITORS\CERAMIC; Project: TI_J7ES_EVM_CP; RoHS: RoHS; Temperature: -55°C+125°C; Tolerance: 5%; Voltage: 16V; Wattage: NA; Weight: 6mg; Datasheet: Y:\MIS_DATABASE\DATASHEETS\CAPACITORS\GCM155R71C104JA55D.PDF
C181 C575 = CAP: CAP CERAMIC 220pF 10V 5% C0G(NP0) 0402; Chkd/date: SHREESHAIL/281105; Crtd /date: MAZHAR/040505; Custom_Duty: 15%; Customs_HS_Code: 85322990; Distributor_name: NA; Distributor_part_number: NA; Footprint Path: Y:\MIS_DATABASE\Library\ALTIUM_TOOL\PCB_FOOTPRINTS\Altium_Footprint_Lib.PcbLib; Height: 0.56MM; Library Path: Y:\MIS_DATABASE\Library\ALTIUM_TOOL\SCHEMATICS_PARTS\MS_DISCRETE_Library.schlib; Mfr_name: AVX CORPORATION; Mfr_part_number: 0402ZA221JAT2A; Mistral Part No: 120009030313-R; Package: 0402; Part #: 101782-1223R; Part_type: CAPACITORS\CERAMIC; Project: JUKEBOX_MAIN; RoHS: RoHS; Temperature: -55°C+125°C; Tolerance: 5%; Voltage: 10V; Wattage: NA; Weight: NA; Datasheet: Y:\MIS_DATABASE\DATASHEETS\CAPACITORS\AVX_MLC.PDF
R84 R289 = RESISTOR: RES 10K 1/16W 1% 0402; Chkd/date: VASANTHA/201216; Crtd /date: GEETHA/290506; Custom_Duty: 15%; Customs_HS_Code: 85332119; Distributor_name: DIGIKEY; Distributor_part_number: 311-10.0KLRTR-ND; Footprint Path: Y:\MIS_DATABASE\Library\ALTIUM_TOOL\PCB_FOOTPRINTS\Altium_Footprint_Lib.PcbLib; Height: 0.40MM; Library Path: Y:\MIS_DATABASE\Library\ALTIUM_TOOL\SCHEMATICS_PARTS\MS_DISCRETE_Library.schlib; Mfr_name: YAGEO AMERICA; Mfr_part_number: RC0402FR-0710KL; Mistral Part No: 110015090015-R; Package: 0402; Part #: 102145-1003R; Part_type: RESISTORS\FIXED; Project: VOCERA; RoHS: RoHS; Temperature: -55°C+155°C; Tolerance: 1%; Voltage: NA; Wattage: 1/16W; Weight: 0.65mg; Datasheet: Y:\MIS_DATABASE\DATASHEETS\RESISTORS\RCXXXXL-SER_MAR18.PDF
U28 U68 = TPS22965DSGT_WSON8_0: IC 6A,16mOHM ON RESISTANCE LOAD SWITCH WSON8; Chkd/date: MANIRAJA/110817; Crtd /date: MANIRAJA/110817; Custom_Duty: 15%; Customs_HS_Code: 85423100; Distributor_name: DIGIKEY; Distributor_part_number: 296-42375-1-ND; Height: 0.80MM; Library Ref: TPS22965DSGT_WSON8; Mfr_name: TEXAS INSTRUMENTS; Mfr_part_number: TPS22965DSGT; Mistral Part No: 142017080006-R; Package: WSON8; Part #: 104267-0001R; Part_type: ICS\POWER\DRIVER; Project: TI_SVB_MAXWELL_DUT; RoHS: RoHS; Temperature: -40°C+105°C; Tolerance: NA; Voltage: NA; Wattage: NA; Weight: 11mg; Datasheet: Y:\MIS_DATABASE\DATASHEETS\ICS\POWER\TPS22965N.PDF
R395-R402 = R_1: Part #: 103158-1002R
R416-R423 = R_1: Part #: 103158-1003R
RJ4-RJ13 = RJUMP3: Part #: 102145-1003R
SW2 = SW_DIP-8: Part #: 101184-0008R
C581 C609 = CAP: Part #: 104448-0220R; Voltage: 6.3V
C90 C94 C497 C594 = Cap_100nF_Cermc_16V_10%_603_4: Part #: 104446-1100R; Voltage: 16V
C597 = CAP: Part #: 104938-0470R; Voltage: 6.3V
C608 C611 = Cap_100nF_Cermc_16V_10%_603_4: Part #: 103885-1220R; Voltage: 50V
C660 = CAP_NP: Part #: 104446-1100R; Voltage: 16V
R297 R298 R301 R311 R312 R314 R318 R324 R325 R329 R330 = RESISTOR: Part #: 102145-4703R
R302 = RESISTOR: RES 22E 1/16W 1% 0402; Chkd/date: SUHAS/290910; Crtd /date: MAZHAR/090909; Cust_part_number: 4700-80047E; Custom_Duty: 15%; Customs_HS_Code: 85332119; Distributor_name: DIGIKEY; Distributor_part_number: 311-22.0LRCT-ND; Footprint Path: Y:\MIS_DATABASE\Library\ALTIUM_TOOL\PCB_FOOTPRINTS\Altium_Footprint_Lib.PcbLib; Height: 0.40MM; Library Path: Y:\MIS_DATABASE\Library\ALTIUM_TOOL\SCHEMATICS_PARTS\MS_DISCRETE_Library.schlib; Mfr_name: YAGEO AMERICA; Mfr_part_number: RC0402FR-0722RL; Mistral Part No: 110009090004-R; Package: 0402; Part #: 102145-2210R; Part_type: RESISTORS\FIXED; Project: VMEFMCD; RoHS: RoHS; Temperature: -55°C+155°C; Tolerance: 1%; Voltage: NA; Wattage: 1/16W; Weight: 0.65mg; Datasheet: Y:\MIS_DATABASE\DATASHEETS\RESISTORS\RCXXXXL-SER_MAR18.PDF
R313 = R: Part #: 102145-1002R
R317 = RESISTOR: Part #: 101370-0001R
U31 = MTFC32GAKAEDQ-AIT: Part #: 105334-0032R
U35 = SN74LVC1G125_0: Part #: 101057-0125R
C21 C60 = CAP_NP: Part #: 103885-1100R; Voltage: 50V
C37 C100 C104 = CAP: Part #: 104724-0101R; Voltage: 25V
C65 C72 = CAP_NP_0: Part #: 104724-0101R; Voltage: 25V
C70 = CAP_NP: Part #: 104903-0220R; Voltage: 50V
C498 = CAP_NP_0: Part #: 104911-0100R; Voltage: 10V
FL1 FL3 = DLW21SN121HQ2: Part #: 104184-1201R
FL26 FL28-FL31 FL35-FL38 = DLW21SN121HQ2: Part #: 104184-9000R
J1 J2 = 1932258-1-USB3: Part #: 104664-0001R
Q1 Q15 = BSS138PS: Part #: 104958-0001R
R26 R56 R75 R95 R264-R266 = R: Part #: 102145-1003R
R33 = R: Part #: 102145-4992R
R39 R40 R48 = R: Part #: 102145-1004R
R43 = R: Part #: 102145-8063R
R44 = R: Part #: 102145-1913R
R47 = R: Part #: 102145-2002R
R49-R51 R55 = R_2: Part #: 101370-0001R
R269 = R: Part #: 102145-1584R
RJ2 = RJUMP3A: Part #: 101370-0001R
TP8 TP12 = TP-30RD13: Part #: TP-30RD13-NO-POP
U7 = TPD3S716-Q1: Part #: 104917-0001R
U11 = TPS254900-Q1: Part #: 104961-0001R-TI
U65 U66 = tpd4e05u06-q1: Part #: 104918-0001R
C833 = CAP: CAP CERAMIC 10uF 16V 10% X5R 0805; Chkd/date: SHREESHAIL/220506; Crtd /date: MAZHAR/150506; Custom_Duty: 15%; Customs_HS_Code: 85322990; Distributor_name: DIGIKEY; Distributor_part_number: 490-3886-1-ND; Footprint Path: Y:\MIS_DATABASE\Library\ALTIUM_TOOL\PCB_FOOTPRINTS\Altium_Footprint_Lib.PcbLib; Height: 1.35MM; Library Path: Y:\MIS_DATABASE\Library\ALTIUM_TOOL\SCHEMATICS_PARTS\MS_DISCRETE_Library.schlib; Mfr_name: MURATA; Mfr_part_number: GRM21BR61C106KE15L; Mistral Part No: 120009030205-R; Package: 0805; Part #: 105027-0101R; Part_type: CAPACITORS\CERAMIC; Project: VOCERA; RoHS: RoHS; Temperature: -55°C+85°C; Tolerance: 10%; Voltage: 16V; Wattage: NA; Weight: 9.5mg; Datasheet: Y:\MIS_DATABASE\DATASHEETS\CAPACITORS\MURATA-GXX-SER_NOV17.PDF
C836 = CAP: CAP CERAMIC 0.1uF 50V 10% X7R 0402; Chkd/date: MANIRAJA/230418; Crtd /date: ALVY/230418; Custom_Duty: 15%; Customs_HS_Code: 85322990; Distributor_name: DIGIKEY; Distributor_part_number: 587-3498-1-ND; Footprint Path: Y:\MIS_DATABASE\Library\ALTIUM_TOOL\PCB_FOOTPRINTS\Altium_Footprint_Lib.PcbLib; Height: 0.55MM; Library Path: Y:\MIS_DATABASE\Library\ALTIUM_TOOL\SCHEMATICS_PARTS\MS_DISCRETE_Library.schlib; Mfr_name: TAIYO YUDEN; Mfr_part_number: UMK105B7104KV-FR; Mistral Part No: 120011100014-R; Package: 0402; Part #: 104910-1100R; Part_type: CAPACITORS\CERAMIC; Project: GC150_PHASE-II_AB; RoHS: RoHS; Temperature: -55°C+125°C; Tolerance: 10%; Voltage: 50V; Wattage: NA; Weight: 0.65mg; Datasheet: Y:\MIS_DATABASE\DATASHEETS\CAPACITORS\UMK105B7104KV-FR.PDF
D15-D24 = DIODE_TPD1E05U06: DIODE 1CH ESD PROTECTION FOR INTERFACE X1SON2; Chkd/date: MANIRAJA/290618; Crtd /date: MANIRAJA/290618; Custom_Duty: 15%; Customs_HS_Code: 85412900; Distributor_name: DIGIKEY; Distributor_part_number: 296-39342-1-ND; Footprint Path: Y:\MIS_DATABASE\Library\ALTIUM_TOOL\PCB_FOOTPRINTS\Altium_Footprint_Lib.PcbLib; Height: 0.45MM; Library Path: Y:\MIS_DATABASE\Library\ALTIUM_TOOL\SCHEMATICS_PARTS\MS_DISCRETE_Library.schlib; Mfr_name: TEXAS INSTRUMENTS; Mfr_part_number: TPD1E05U06DPYT; Mistral Part No: 130018060037-R; Package: X1SON2; Part #: 104410-0001R; Part_type: DIODE\TVS; Project: GOLDEN-I LITE; RoHS: RoHS; Temperature: -40°C+125°C; Tolerance: NA; Voltage: NA; Wattage: NA; Weight: 1mg; Datasheet: Y:\MIS_DATABASE\DATASHEETS\DISCRETES\DIODES\TPDXE05U06.PDF
J18 = CON20_USB_F_TI: CON MINI USB-DISPLAY PORT 20POS FEMALE RT TH; Chkd/date: MANIRAJA/280518; Crtd /date: VASANTHA/05115; Custom_Duty: 24%; Customs_HS_Code: 85369090; Distributor_name: DIGIKEY; Distributor_part_number: WM19271CT-ND; Footprint Path: Y:\MIS_DATABASE\Library\ALTIUM_TOOL\PCB_FOOTPRINTS\Altium_Footprint_Lib.PcbLib; Height: 6.98MM; Library Path: Y:\MIS_DATABASE\Library\ALTIUM_TOOL\SCHEMATICS_PARTS\MS_CONNECTOR_Library.schlib; Library Ref: CON20_USB_F; Mfr_name: MOLEX; Mfr_part_number: 472720001; Mistral Part No: 150015110011-R; Package: THRU-HOLE; Part #: 105210-0020R; Part_type: CONNECTOR\USB; Project: LRDE_PSPU; RoHS: RoHS; Temperature: -20°C+85°C; Tolerance: NA; Voltage: NA; Wattage: NA; Weight: 2.719g; Datasheet: Y:\MIS_DATABASE\DATASHEETS\CONNECTORS\47272XXX.PDF
R240 R241 R458 R464 R465 = RESISTOR: RES 100K 1/10W 5% 0402; Chkd/date: VASANTHA/291216; Crtd /date: GEETHA/190406; Custom_Duty: 15%; Customs_HS_Code: 85332119; Distributor_name: DIGIKEY; Distributor_part_number: P100KJCT-ND; Footprint Path: Y:\MIS_DATABASE\Library\ALTIUM_TOOL\PCB_FOOTPRINTS\Altium_Footprint_Lib.PcbLib; Height: 0.40MM; Library Path: Y:\MIS_DATABASE\Library\ALTIUM_TOOL\SCHEMATICS_PARTS\MS_DISCRETE_Library.schlib; Mfr_name: PANASONIC-ECG; Mfr_part_number: ERJ-2GEJ104X; Mistral Part No: 110009030177-R; Package: 0402; Part #: 102145-1004R; Part_type: RESISTORS\FIXED; Project: RED EYE; RoHS: RoHS; Temperature: -55°C+155°C; Tolerance: 5%; Voltage: NA; Wattage: 1/10W; Weight: 0.8mg; Datasheet: Y:\MIS_DATABASE\DATASHEETS\RESISTORS\PAN-ERJSER_NOV17.PDF
U78 = TPD1E10B09: Part #: 104615-0001R

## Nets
DGND: C21.1 C37.2 C60.1 C65.2 C70.2 C72.2 C90.2 C94.2 C98.2 C99.2 C100.2 C104.2 C105.2 C106.2 C111.2 C114.2 C115.2 C120.2 C121.2 C124.2 C141.2 C145.2 C153.2 C154.2 C159.2 C165.2 C166.2 C168.2 C169.2 C181.2 C183.2 C497.2 C498.2 C519.2 C520.2 C527.2 C528.2 C535.2 C536.2 C538.2 C543.2 C544.2 C545.2 C546.2 C549.2 C550.2 C553.2 C559.2 C560.2 C565.2 C569.2 C570.2 C571.2 C575.2 C579.2 C581.2 C594.2 C597.2 C608.2 C609.2 C611.2 C660.1 C833.2 C836.2 D15.2(GND) D16.2(GND) D17.2(GND) D18.2(GND) D19.2(GND) D20.2(GND) D21.2(GND) D22.2(GND) D23.2(GND) D24.2(GND) J1.4(GND4) J1.7(GND8) J1.G1 J1.G2 J2.4(GND4) J2.7(GND8) J2.G1 J2.G2 J18.2(GND) J18.5(GND) J18.8(GND) J18.11(GND) J18.16(GND) J18.19(RETURN) J18.SH1 J18.SH2 J18.SH3 J18.SH4 Q1.1(S2) Q15.1(S2) Q15.4(S2) R26.2 R43.2 R44.2 R47.2 R56.2 R75.2 R84.1 R95.2 R241.1 R265.1 R269.2 R285.1 R289.1 R301.2 R303.2 R306.2 R399.1 R400.1 R401.1 R402.1 R416.2 R417.2 R418.2 R419.2 R456.2 R457.2 R458.1 RJ2.3 RJ4.1 RJ5.1 RJ6.1 RJ7.1 RJ8.1 RJ9.1 RJ10.1 RJ11.1 RJ12.3 RJ13.3 U7.4(GND) U7.13(GND) U11.11(GND) U11.21(PAD) U20.5(REFGND1) U20.6(REFGND2) U20.21(FB_B2) U20.36(VBACKUP) U20.38(OSC32KIN) U20.57(GND) U28.5(GND) U28.9(EP) U31.G2(VSS.1) U31.G3(VSS.2) U31.G4(VSS.3) U31.G5(VSS.4) U31.G6(VSS.5) U31.G7(VSS.6) U31.G8(VSS.7) U31.G9(VSS.8) U31.H2(VSSQ.1) U31.H9(VSSQ.2) U31.J5(VSS.9) U31.L3(VSSQ.3) U31.L8(VSSQ.4) U31.M4(VSSQ.5) U31.M7(VSSQ.6) U31.P2(VSSQ.7) U31.P9(VSSQ.8) U35.2(I) U35.3(GND) U65.3(GND) U65.8(GND) U66.3(GND) U66.8(GND) U68.5(GND) U68.9(EP) U78.2(GND) ; also on sheet 8 9 10 11 12 13 14 15 17 18 19 20 21 22 23 30 31 32 33 34 35 36 37 38 39 40
V3V3_DP0: C833.1 C836.1 J18.20(PWR) ; also on sheet 40
VBUS2_5V0: C21.2 J1.1(VBUS) U7.2(VBUS_CON) U7.3(VBUS_SON)
VBUS_USBC_CONN: C60.2 C65.1 C72.1 J2.1(VBUS) R33.1 U11.15(OUT) U11.16(OUT) ; also on sheet 15
VCCA_3V3: C105.1 C106.1 C120.1 C153.1 C154.1 C527.1 C528.1 C535.1 C536.1 C538.1 C543.1 C544.1 C546.1 C549.1 C553.1 C559.1 C560.1 C565.1 U20.4(VCCA) U20.8(PVIN_LDO4) U20.10(PVIN_LDO3) U20.12(PVIN_LDO12) U20.17(PVIN_B2) U20.26(PVIN_B1) U20.35(PVIN_B5) U20.45(PVIN_B3) U20.54(PVIN_B4) U68.1(VIN1) U68.2(VIN2) U68.4(VBIAS) ; also on sheet 23
VDD_CORE_0V8: C98.1 C99.1 C168.1 C169.1 C519.1 C520.1 C569.1 C570.1 L28.2 L29.2 L34.2 L35.2 U20.22(FB_B1) ; also on sheet 17 19
VDD_CORE_0V8_REG_SW1: L28.1 U20.27(SW_B1A) U20.28(SW_B1B)
VDD_CORE_0V8_REG_SW2: L29.1 U20.15(SW_B2A) U20.16(SW_B2B)
VDD_CORE_0V8_REG_SW3: L34.1 U20.43(SW_B3A) U20.44(SW_B3B)
VDD_CORE_0V8_REG_SW4: L35.1 U20.55(SW_B4A) U20.56(SW_B4B)
VDD_DDR_1V1: R132.1 ; also on sheet 11 19 23
VDD_IO_1V8: C115.1 C608.1 C609.1 R297.1 R298.1 R311.1 R312.1 R313.2 R314.1 R318.1 R324.1 R325.1 R329.1 R330.1 U20.9(VOUT_LDO3) U31.H3(VCCQ.1) U31.H8(VCCQ.2) U31.L2(VCCQ.3) U31.L4(VCCQ.4) U31.L7(VCCQ.5) U31.L9(VCCQ.6) U31.P3(VCCQ.7) U31.P8(VCCQ.8) ; also on sheet 18
VDD_IO_3V3: C165.1 C166.1 C498.1 C597.1 C611.1 C660.2 R39.2 R40.2 R240.2 R266.1 R395.1 R396.1 R397.1 R398.1 R464.2 R465.2 RJ2.1 RJ4.3 RJ5.3 RJ6.3 RJ7.3 U7.9(VIN) U28.7(VOUT1) U28.8(VOUT2) U31.F2(VCC.1) U31.F3(VCC.2) U31.F4(VCC.3) U31.F5(VCC.4) U31.F6(VCC.5) U31.F7(VCC.6) U31.F8(VCC.7) U31.F9(VCC.8) U35.5(VCC) ; also on sheet 10 15 16 18 21 30 31 32 34 35 36 37 38 39 40
VDD_MCUIO_3V3: C550.1 C571.1 C579.1 R420.2 R421.2 R422.2 R423.2 RJ8.3 RJ9.3 RJ10.3 RJ11.3 RJ12.1 RJ13.1 U20.48(VIO_IN) U68.7(VOUT1) U68.8(VOUT2) ; also on sheet 14 18 23 34 37 39
VDD_RAM_0V85: C124.1 C545.1 L30.2 U20.37(FB_B5) ; also on sheet 17
VDD_RAM_0V85_REG_SW: L30.1 U20.34(SW_B5A)
VDD_SD_DV: C111.1 U20.13(VOUT_LDO1) ; also on sheet 18 36
VDDI_MMC2: C581.1 C594.1 U31.E4(VDDIM)
VINT_LEOA_1V8: R277.1 ; also on sheet 23
VINT_LEOB_1V8: C145.1 U20.2(VOUT_LDOVINT)
A2B_MCU_SPI_CLK: RJ8.2 ; also on sheet 14 39
A2B_MCU_SPI_D0: RJ9.2 ; also on sheet 14 39
A2B_MCU_SPI_D1: RJ10.2 ; also on sheet 14 39
A2B_WKUP_GPIO_0: R423.1 SW2.1(A1) ; also on sheet 14 39
A2B_WKUP_GPIO_1: R422.1 SW2.2(A2) ; also on sheet 14 39
A2B_WKUP_GPIO_2: R421.1 SW2.3(A3) ; also on sheet 14 39
A2B_WKUP_GPIO_15: RJ11.2 ; also on sheet 14 39
BOOTMODE0: R419.1 SW2.5(A5) ; also on sheet 16
BOOTMODE1: RJ4.2 ; also on sheet 16
BOOTMODE2: RJ5.2 ; also on sheet 16
BOOTMODE3: RJ6.2 ; also on sheet 16
BOOTMODE4: R418.1 SW2.6(A6) ; also on sheet 14
BOOTMODE5: R417.1 SW2.7(A7) ; also on sheet 14
BOOTMODE6: R416.1 SW2.8(A8) ; also on sheet 16
BOOTMODE7: RJ7.2 ; also on sheet 16
CON_DP0_AUX_N: D19.1(I/O) FL26.3 J18.17(AUX_CH_N) R240.1
CON_DP0_AUX_P: D20.1(I/O) FL26.2 J18.15(AUX_CH_P) R241.2
CON_DP0_HPD: J18.18(HPD) Q15.2(G2) R458.2 U78.1(IO)
CON_DP0_TX0_N: D23.1(I/O) FL31.3 J18.3(ML_L0_N)
CON_DP0_TX0_P: D24.1(I/O) FL31.2 J18.1(ML_L0_P)
CON_DP0_TX1_N: D18.1(I/O) FL28.3 J18.6(ML_L1_N)
CON_DP0_TX1_P: D17.1(I/O) FL28.2 J18.4(ML_L1_P)
CON_DP0_TX2_N: D21.1(I/O) FL30.3 J18.9(ML_L2_N)
CON_DP0_TX2_P: D22.1(I/O) FL30.2 J18.7(ML_L2_P)
CON_DP0_TX3_N: D15.1(I/O) FL29.3 J18.12(ML_L3_N)
CON_DP0_TX3_P: D16.1(I/O) FL29.2 J18.10(ML_L3_P)
CONN_USB1_DM: FL3.2 J2.2(D-)
CONN_USB1_DP: FL3.3 J2.3(D+)
CONN_USB2_DM: FL1.3 J1.2(D-)
CONN_USB2_DP: FL1.2 J1.3(D+)
CONN_USB_RXN0: FL36.3 J2.5(StdA_SSRX-) U65.5(D2-) U65.6(NC6)
CONN_USB_RXN1: FL38.3 J1.5(StdA_SSRX-) U66.5(D2-) U66.6(NC6)
CONN_USB_RXP0: FL36.2 J2.6(StdA_SSRX+) U65.4(D2+) U65.7(NC7)
CONN_USB_RXP1: FL38.2 J1.6(StdA_SSRX+) U66.4(D2+) U66.7(NC7)
CONN_USB_TXN0: FL35.3 J2.8(StdA_SSTX-) U65.2(D1-) U65.9(NC9)
CONN_USB_TXN1: FL37.3 J1.8(StdA_SSTX-) U66.2(D1-) U66.9(NC9)
CONN_USB_TXP0: FL35.2 J2.9(StdA_SSTX+) U65.1(D1+) U65.10(NC10)
CONN_USB_TXP1: FL37.2 J1.9(StdA_SSTX+) U66.1(D1+) U66.10(NC10)
DP0_AUX_N: FL26.4 ; also on sheet 9
DP0_AUX_P: FL26.1 ; also on sheet 9
DP0_CONFIG1: J18.13(CONFIG1) R456.1
DP0_CONFIG2: J18.14(CONFIG2) R457.1
DP0_HPD: Q15.3(D2) R465.1 ; also on sheet 15
DP0_TX0_N: FL31.4 ; also on sheet 9
DP0_TX0_P: FL31.1 ; also on sheet 9
DP0_TX1_N: FL28.4 ; also on sheet 9
DP0_TX1_P: FL28.1 ; also on sheet 9
DP0_TX2_N: FL30.4 ; also on sheet 9
DP0_TX2_P: FL30.1 ; also on sheet 9
DP0_TX3_N: FL29.4 ; also on sheet 9
DP0_TX3_P: FL29.1 ; also on sheet 9
EN_3V3IO_LDSW: R84.2 U20.53(GPIO11) U28.3(ON) ; also on sheet 21 34 40
EN_MCU3V3IO_LDSW: R289.2 U68.3(ON) ; also on sheet 23
H_DDR_RET_1V1: R132.2 U20.47(GPIO4) ; also on sheet 11
H_MCU_INT#: U20.14(nINT) ; also on sheet 14 23
LEOA_SCLK: U20.23(GPIO5) ; also on sheet 23
LEOA_SDATA: U20.24(GPIO6) ; also on sheet 23
LEOB_GPIO1: TP16.1 U20.32(GPIO1)
LEOB_GPIO3: TP32.1 U20.46(GPIO3)
LEOB_GPIO7: TP14.1 U20.18(GPIO7)
LEOB_GPIO8: TP19.1 U20.41(GPIO8)
LEOB_GPIO9: TP13.1 U20.19(GPIO9)
LEOB_GPIO10: R285.2 R286.1 U20.42(GPIO10)
LS2_CT: C181.1 U28.6(CT)
LS3_CT: C575.1 U68.6(CT)
MCU_BOOTMODE6: R420.1 SW2.4(A4) ; also on sheet 14
MCU_BOOTMODE8: RJ12.2 ; also on sheet 14
MCU_BOOTMODE9: RJ13.2 ; also on sheet 14
MCU_DMTIMER9: R286.2 ; also on sheet 14
MMC0_CLK: R317.1 R318.2 ; also on sheet 10
MMC0_CMD: R314.2 U31.P5(CMD) ; also on sheet 10
MMC0_DAT0: R297.2 U31.K2(DAT0) ; also on sheet 10
MMC0_DAT1: R298.2 U31.N2(DAT1) ; also on sheet 10
MMC0_DAT2: R311.2 U31.K3(DAT2) ; also on sheet 10
MMC0_DAT3: R312.2 U31.N3(DAT3) ; also on sheet 10
MMC0_DAT4: R325.2 U31.N8(DAT4) ; also on sheet 10
MMC0_DAT5: R324.2 U31.K8(DAT5) ; also on sheet 10
MMC0_DAT6: R330.2 U31.N9(DAT6) ; also on sheet 10
MMC0_DAT7: R329.2 U31.K9(DAT7) ; also on sheet 10
MMC0_DS: R302.1 ; also on sheet 10
PG_LM53603: R48.2 U11.7(EN) ; also on sheet 22
PMICB_EN: R277.2 U20.20(nPWRON/ENABLE)
PMICB_FB3: R303.1 R304.1 U20.49(FB_B3)
PMICB_FB4: R305.1 R306.1 U20.50(FB_B4)
SEL_SDIO_3V3_1V8n: TP17.1 U20.33(GPIO2) ; also on sheet 16
SOC_PORZ_OUT: U35.1(OE) ; also on sheet 14 37 38
SOC_WKUP_I2C0_SCL: U20.31(SCL_I2C1/SCK_SPI) ; also on sheet 14 23
SOC_WKUP_I2C0_SDA: U20.30(SDA_I2C1/SDI_SPI) ; also on sheet 14 23
USB0_CS: R55.1 ; also on sheet 22
USB0_DATA_N: U11.4(DM_OUT) ; also on sheet 15
USB0_DATA_P: U11.5(DP_OUT) ; also on sheet 15
USB0_DRVVBUS: R49.1 R50.1 R56.1 ; also on sheet 15
USB0_ID: R95.1 ; also on sheet 15
USB0_IMON: R51.1 ; also on sheet 13
USB0_SS_RX2_N: FL36.4 ; also on sheet 9
USB0_SS_RX2_P: FL36.1 ; also on sheet 9
USB0_SS_TX2_N: FL35.4 ; also on sheet 9
USB0_SS_TX2_P: FL35.1 ; also on sheet 9
USB0_STATUS: R39.1 U11.17(STATUS) ; also on sheet 15
USB0_VBUS_OCN: R40.1 U11.18(FAULT) ; also on sheet 15
USB1_DM: FL3.1 U11.14(DM_IN)
USB1_DP: FL3.4 U11.13(DP_IN)
USB1_HUB_D_N: U7.12(D-) ; also on sheet 38
USB1_HUB_D_P: U7.11(D+) ; also on sheet 38
USB1_HUB_PWRCLT1: Q1.2(G2) R26.1 ; also on sheet 38
USB1_ID: R75.1 ; also on sheet 15
USB1_SS_RX1_N: FL38.4 ; also on sheet 9
USB1_SS_RX1_P: FL38.1 ; also on sheet 9
USB1_SS_TX1_N: FL37.4 ; also on sheet 9
USB1_SS_TX1_P: FL37.1 ; also on sheet 9
USB2_DM: FL1.4 U7.5(VD-)
USB2_DP: FL1.1 U7.6(VD+)
VDA_PLL_1V8: C121.1 U20.7(VOUT_LDO4) ; also on sheet 17
VDA_USB_3V3: C114.1 U20.11(VOUT_LDO2) ; also on sheet 17
VRTC_LEOB_1V8: C141.1 R283.1 U20.3(VOUT_LDOVRTC)
VSYS_3V3: C159.1 C183.1 U28.1(VIN1) U28.2(VIN2) U28.4(VBIAS) ; also on sheet 17 22 23 34 40
VUSB_5V0: C37.1 C94.1 C100.1 C104.1 C497.1 R48.1 R264.1 U7.14(VBUS_SYS) U7.15(VBUS_SYS) U11.2(IN) U11.3(IN) ; also on sheet 22
N22073312: R317.2 U31.P6(CLK)
N22073335: R313.1 U31.M5(RSTN) U35.4(O)
N28964551: R301.1 R302.2 U31.K5(DS)
N29520912: R402.2 SW2.16(B1)
N29520937: R401.2 SW2.15(B2)
N29520962: R400.2 SW2.14(B3)
N29520987: R399.2 SW2.13(B4)
N29521012: R398.2 SW2.12(B5)
N29521037: R397.2 SW2.11(B6)
N29521062: R396.2 SW2.10(B7)
N29521082: R395.2 SW2.9(B8)
N29622583: R283.2 U20.40(OSC32KCAP)
N30080305: R269.1 U7.16(IADJ)
N30080322: R266.2 TP8.1(TP) U7.10(FLT)
N30080336: Q1.6(D2) R264.2 U7.7(VEN)
N30080339: R265.2 U7.8(DEN)
N30703324: C70.1 R33.2 U11.12(BIAS)
N30703458: R43.1 U11.19(ILIM_LO)
N30703463: R44.1 U11.20(ILIM_HI)
N30745719: C90.1 R47.1 R51.2 TP12.1(TP) U11.1(IMON)
N30746595: RJ2.2 U11.10(OVP_SEL)
N31225374: R55.2 U11.6(CS)
N31313642: R49.2 U11.8(CTL1)
N31313645: R50.2 U11.9(CTL2)
N31987713: R304.2 TP37.1(TP)
N31987901: R305.2 TP36.1(TP)
N33430702: Q15.5(G2) Q15.6(D2) R464.1

Not connected (* = marked no-connect by the designer): Q1 3(D2)* 4(S2)* 5(G2)*; U7 1(NC)*; U20 1(AMUXOUT)* 25(nRSTOUT)* 29(EN_DRV)* 39(OSC32KOUT)* 51(VSYS_SENSE)* 52(OVPGDRV)*; U31 A1(NC.1) A2(NC.2) A9(NC.3) A10(NC.4) B1(NC.5) B10(NC.6) D2(RFU.1) D3(RFU.2) D4(RFU.3) D5(RFU.4) D6(RFU.5) D7(RFU.6) D8(RFU.7) D9(RFU.8) E2(RFU.9) E3(RFU.10) E5(RFU.11) E6(RFU.12) E7(RFU.13) E8(RFU.14) E9(RFU.15) H4(RFU.16) H5(RFU.17) H6(RFU.18) H7(RFU.19) J2(RFU.20) J3(RFU.21) J4(RFU.22) J6(RFU.23) J7(RFU.24) J8(RFU.25) J9(RFU.26) K4(RFU.27) K6(RFU.28) K7(RFU.29) L5(RFU.30) L6(RFU.31) M2(RFU.32) M3(RFU.33) M6(RFU.34) M8(RFU.35) M9(RFU.36) N4(RFU.37) N5(RFU.38) N6(RFU.39) N7(RFU.40) P4(RFU.41) P7(RFU.42) T1(NC.7) T10(NC.8) U1(NC.9) U2(NC.10) U9(NC.11) U10(NC.12)

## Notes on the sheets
sheet 24
- PMIC - B
- PCB Note:
  For multi-phase Buck converter configs, route remote
  sense feedback as follows:
     1. Pseudo differential pair traces on same layer &
  next to primarily power plane segment. Avoid routing near
  to any noisy/switching signals.
     2. Connect each trace, as close as possible, to power
  & Gnd vias or across Dcap in middle of SOC power ball
  group.
     3. Trace widths = 4-8mil & separation distance =
  8-50mil, try to keep traces near each other as best as
  possible while
  SCH Note:
     1. For 3 & 4 phase Buck converter configs, the
  unused feedback sense inputs on Buck 3 & 4 can
  be optionally re-assigned to provide additional "external
  voltage monitoring" for functional safety coverage, see
  PMIC data sheet for details.
  PCB Note:
   For single-phase Buck converters, route remote sense
  feedback as follows:
     1. Single-ended traces on same layer & next to
  primarily power plane segment as best as possible. Avoid
  routing near to any noisy/switching signals.
     2. Connect each trace, as close as possible, to a
  power via near in middle of SOC power ball group.
     3. Trace widths = 4-8mil"
- / Low-side of pseudo diff trace pair
  used for remote sense at point of load
- PMIC-B uses NVM to set I2C ADDR:
  0x4C, 0x4D, 0x4E & 0x4F
sheet 25
- LOAD SWITCHES
- 4A
- 4A
sheet 26
- BOOT MODE SELECTION
- L
- L
- BACKUP BOOT MODE CONFIG
- L
- 19.2MHz
- L
- L
- L
- BACKUP BOOTMODE
- L
- L
- H
- POST BYPASS
- H
- H
- H
- H
- UART/NO-BOOT
- H
- MCU ONLY
- L
- PRIMARY BOOT MODE B
- L
- L
- L
- PRIMARY BOOT MODE CONFIG
sheet 27
- MEM eMMC
- 100BALL BGA 14mmX18mm, 1mm BALL PITCH
  MTFC32GAKAEDQ-AIT - V5.0
  MTFC32GAPALNA-AIT - V5.1
  MTFC32GAPALNA-AAT - V5.1
sheet 28
- USB PORT FOR DEBUG
- HIGHSPEED A - HOST
- USB HOST PORT WITH CHARGE
- PULL DOWN FOR HOST
- SUPERSPEED A - HOST WITH CHARGE SUPPORT
sheet 29
- DISPLAY PORT INTERFACE
- Display Port Connector1
- 100E
- 3.3V@500mA
- 100E
- 100E
- 100E
- Silkscreen: "DISPLAY
  PORT CONN1"
- REVB
- PCB Note: Place the ESD diodes close to DISPLAY  PORT CONN1
- 100E
- REV B, BLOCK DISPLAY HPD UNTIL SOC I/O POWER
